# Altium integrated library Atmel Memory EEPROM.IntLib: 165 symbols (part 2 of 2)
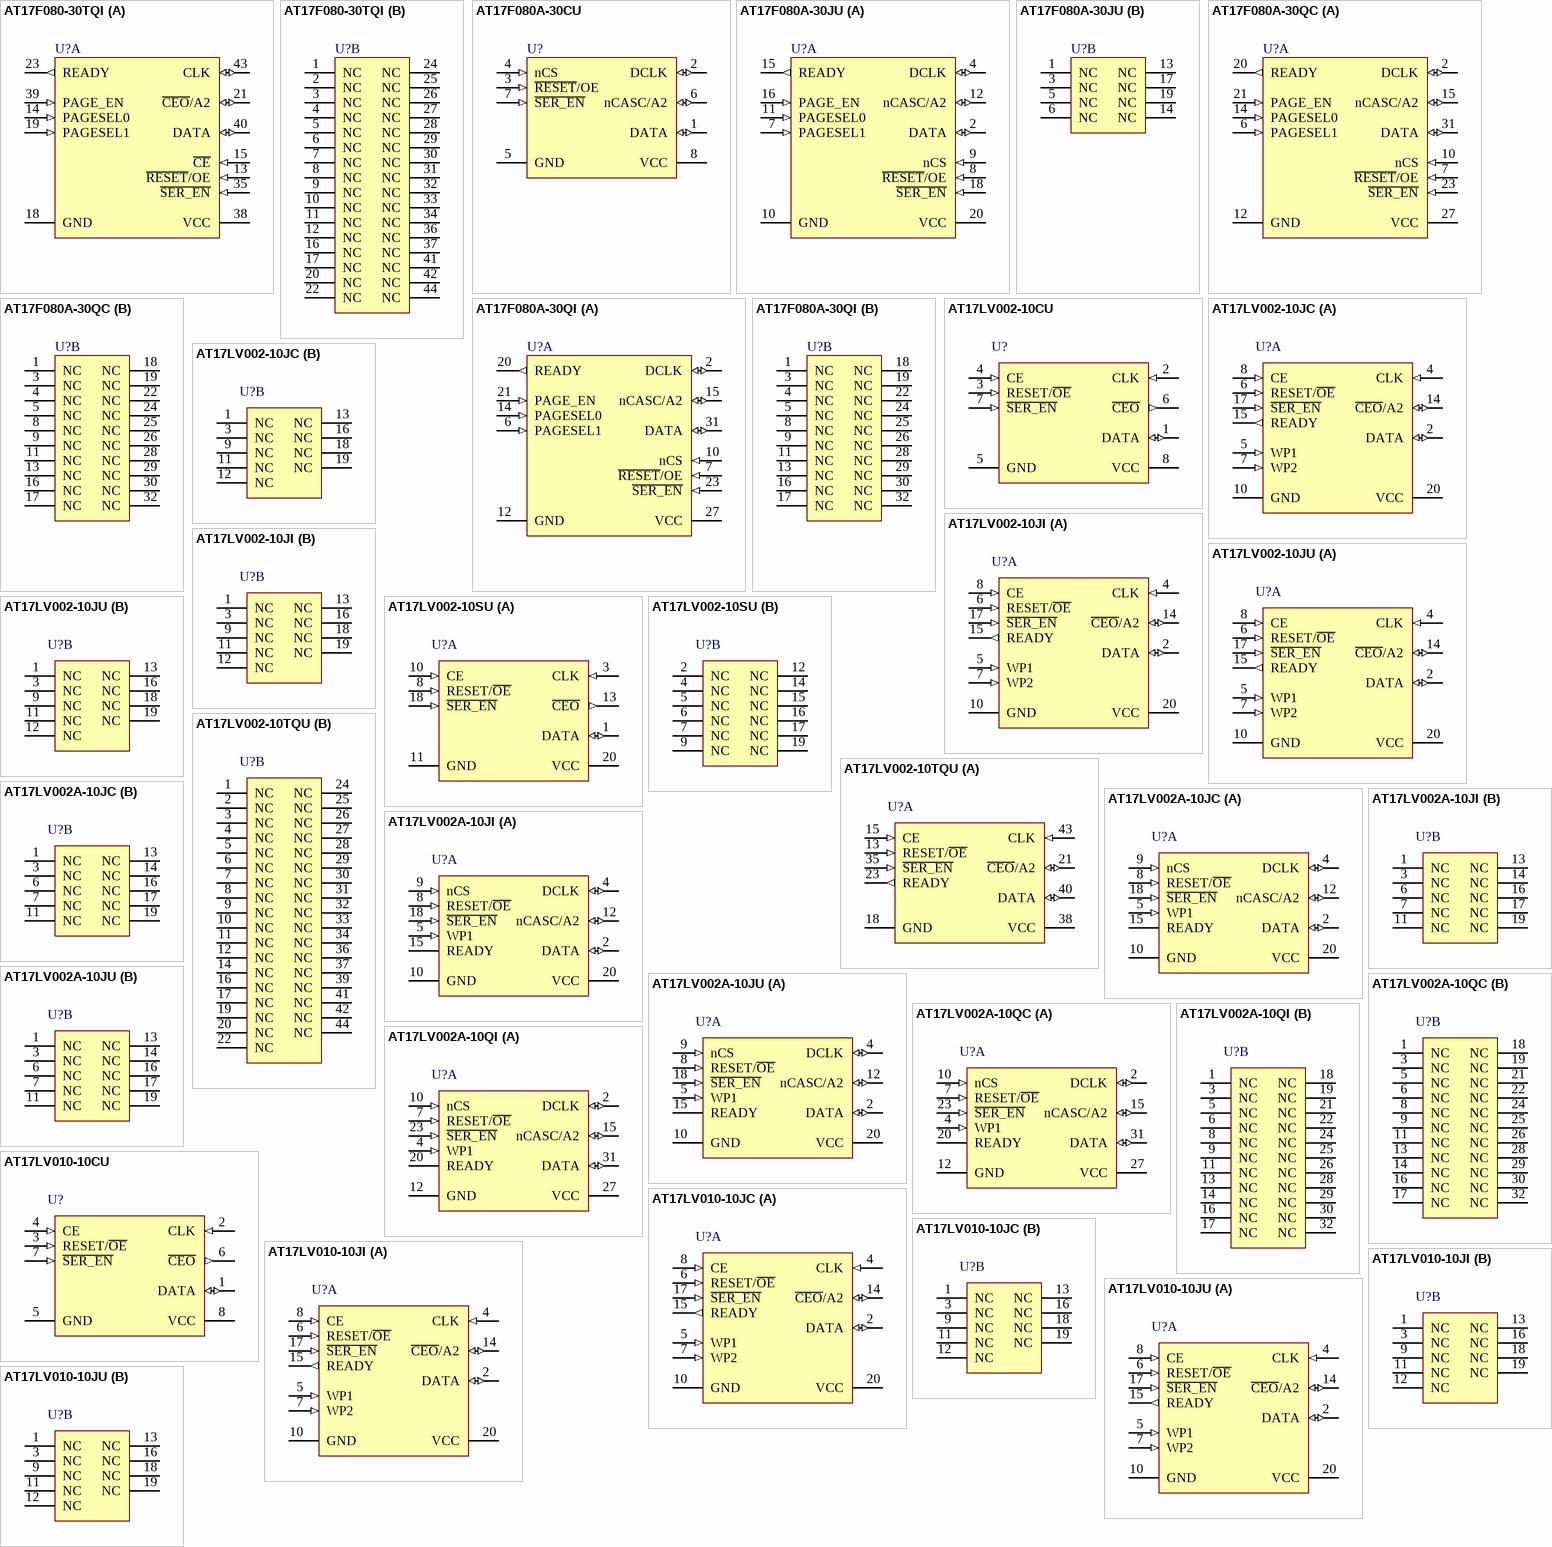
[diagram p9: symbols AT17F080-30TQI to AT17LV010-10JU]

## AT17LV010-10JU
designator U?
FPGA Configuration EEPROM Memory, 1-MBit Memory, 20-Pin PLCC, Industrial Grade (-40°C to 85°C), Pb-Free
footprint 20J_N (Leaded Chip Carrier, 20-Leads, Body 9x9mm, Pitch 1.27mm, IPC Medium Density)
footprint 20J_L (Leaded Chip Carrier, 20-Leads, Body 9x9mm, Pitch 1.27mm, IPC High Density)
footprint 20J_M (Leaded Chip Carrier, 20-Leads, Body 9x9mm, Pitch 1.27mm, IPC Low Density)
part A pins: 2 DATA (io), 4 CLK (in), 5 WP1 (in), 6 RESET/~{OE} (in), 7 WP2 (in), 8 CE (in), 10 GND (power), 14 ~{CEO}/A2 (io), 15 READY (out), 17 ~{SER_EN} (in), 20 VCC (power)
part B pins: 1 NC, 3 NC, 9 NC, 11 NC, 12 NC, 13 NC, 16 NC, 18 NC, 19 NC

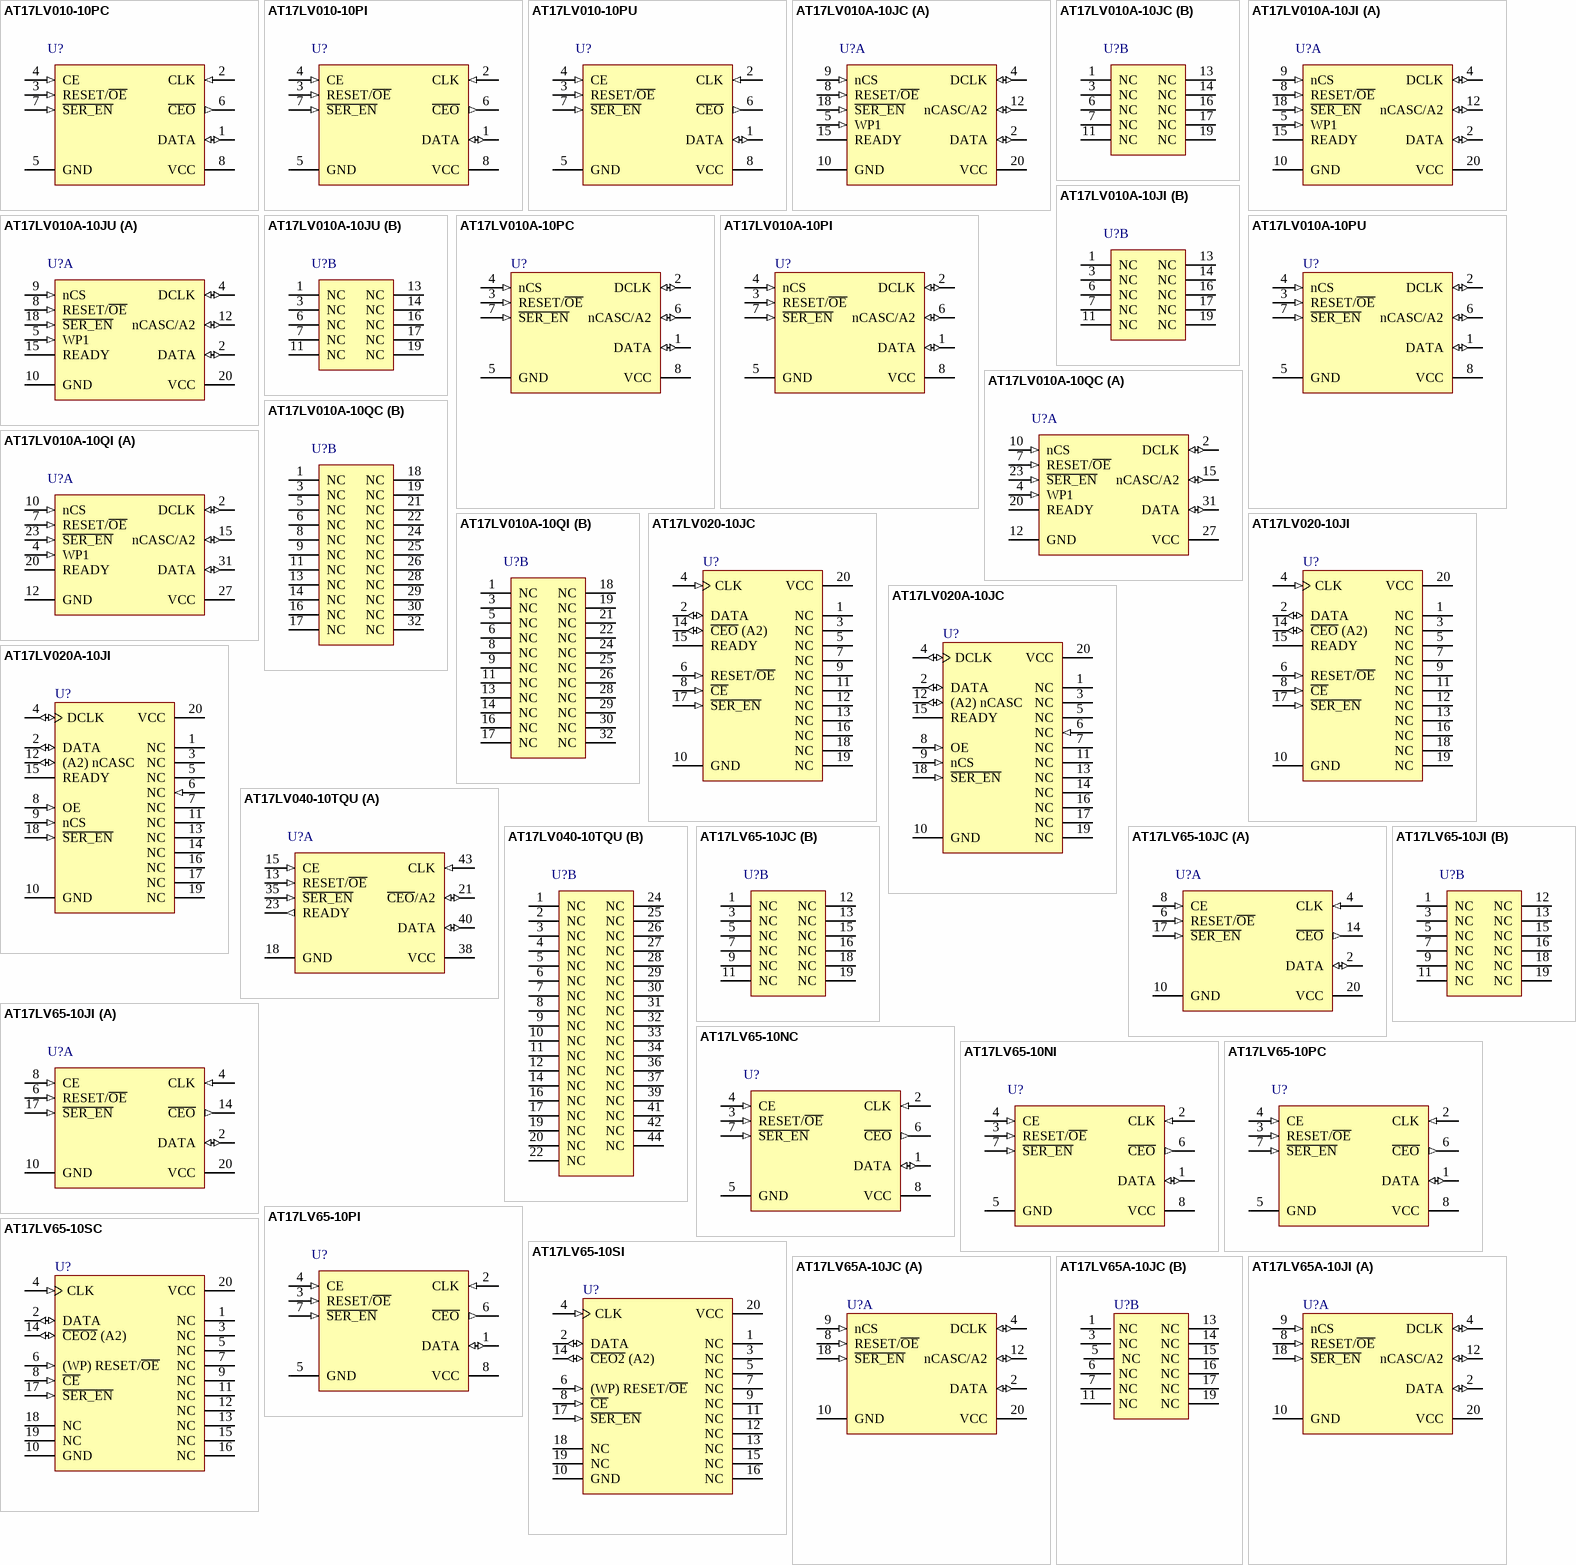
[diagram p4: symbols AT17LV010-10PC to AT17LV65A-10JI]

## AT17LV010-10PC
designator U?
FPGA Configuration EEPROM Memory, 1-MBit Memory, 8-Pin PDIP, Commercial Grade (0°C to 70°C)
footprint 8P3 (DIP, 8-Leads, Row Spacing 7.62mm, Pitch 2.54mm, Body 9.59x6.61mm)
pins: 1 DATA (io), 2 CLK (in), 3 RESET/~{OE} (in), 4 CE (in), 5 GND (power), 6 ~{CEO} (out), 7 ~{SER_EN} (in), 8 VCC (power)

## AT17LV010-10PI
designator U?
FPGA Configuration EEPROM Memory, 1-MBit Memory, 8-Pin PDIP, Industrial Grade (-40°C to 85°C)
footprint 8P3 (DIP, 8-Leads, Row Spacing 7.62mm, Pitch 2.54mm, Body 9.59x6.61mm)
pins: 1 DATA (io), 2 CLK (in), 3 RESET/~{OE} (in), 4 CE (in), 5 GND (power), 6 ~{CEO} (out), 7 ~{SER_EN} (in), 8 VCC (power)

## AT17LV010-10PU
designator U?
FPGA Configuration EEPROM Memory, 1-MBit Memory, 8-Pin PDIP, Industrial Grade (-40°C to 85°C), Pb-Free
footprint 8P3 (DIP, 8-Leads, Row Spacing 7.62mm, Pitch 2.54mm, Body 9.59x6.61mm)
pins: 1 DATA (io), 2 CLK (in), 3 RESET/~{OE} (in), 4 CE (in), 5 GND (power), 6 ~{CEO} (out), 7 ~{SER_EN} (in), 8 VCC (power)

## AT17LV010A-10JC
designator U?
FPGA Configuration EEPROM Memory, 1-MBit Memory, 20-Pin PLCC, Commercial Grade (0°C to 70°C)
footprint 20J_N (Leaded Chip Carrier, 20-Leads, Body 9x9mm, Pitch 1.27mm, IPC Medium Density)
footprint 20J_L (Leaded Chip Carrier, 20-Leads, Body 9x9mm, Pitch 1.27mm, IPC High Density)
footprint 20J_M (Leaded Chip Carrier, 20-Leads, Body 9x9mm, Pitch 1.27mm, IPC Low Density)
part A pins: 2 DATA (io), 4 DCLK (io), 5 WP1 (in), 8 RESET/~{OE} (in), 9 nCS (in), 10 GND (power), 12 nCASC/A2 (io), 15 READY (oc), 18 ~{SER_EN} (in), 20 VCC (power)
part B pins: 1 NC, 3 NC, 6 NC, 7 NC, 11 NC, 13 NC, 14 NC, 16 NC, 17 NC, 19 NC

## AT17LV010A-10JI
designator U?
FPGA Configuration EEPROM Memory, 1-MBit Memory, 20-Pin PLCC, Industrial Grade (-40°C to 85°C)
footprint 20J_N (Leaded Chip Carrier, 20-Leads, Body 9x9mm, Pitch 1.27mm, IPC Medium Density)
footprint 20J_L (Leaded Chip Carrier, 20-Leads, Body 9x9mm, Pitch 1.27mm, IPC High Density)
footprint 20J_M (Leaded Chip Carrier, 20-Leads, Body 9x9mm, Pitch 1.27mm, IPC Low Density)
part A pins: 2 DATA (io), 4 DCLK (io), 5 WP1 (in), 8 RESET/~{OE} (in), 9 nCS (in), 10 GND (power), 12 nCASC/A2 (io), 15 READY (oc), 18 ~{SER_EN} (in), 20 VCC (power)
part B pins: 1 NC, 3 NC, 6 NC, 7 NC, 11 NC, 13 NC, 14 NC, 16 NC, 17 NC, 19 NC

## AT17LV010A-10JU
designator U?
FPGA Configuration EEPROM Memory, 1-MBit Memory, 20-Pin PLCC, Industrial Grade (-40°C to 85°C), Pb-Free
footprint 20J_N (Leaded Chip Carrier, 20-Leads, Body 9x9mm, Pitch 1.27mm, IPC Medium Density)
footprint 20J_L (Leaded Chip Carrier, 20-Leads, Body 9x9mm, Pitch 1.27mm, IPC High Density)
footprint 20J_M (Leaded Chip Carrier, 20-Leads, Body 9x9mm, Pitch 1.27mm, IPC Low Density)
part A pins: 2 DATA (io), 4 DCLK (io), 5 WP1 (in), 8 RESET/~{OE} (in), 9 nCS (in), 10 GND (power), 12 nCASC/A2 (io), 15 READY (oc), 18 ~{SER_EN} (in), 20 VCC (power)
part B pins: 1 NC, 3 NC, 6 NC, 7 NC, 11 NC, 13 NC, 14 NC, 16 NC, 17 NC, 19 NC

## AT17LV010A-10PC
designator U?
FPGA Configuration EEPROM Memory, 1-MBit Memory, 8-Pin PDIP, Commercial Grade (0°C to 70°C)
footprint 8P3 (DIP, 8-Leads, Row Spacing 7.62mm, Pitch 2.54mm, Body 9.59x6.61mm)
pins: 1 DATA (io), 2 DCLK (io), 3 RESET/~{OE} (in), 4 nCS (in), 5 GND (power), 6 nCASC/A2 (io), 7 ~{SER_EN} (in), 8 VCC (power)

## AT17LV010A-10PI
designator U?
FPGA Configuration EEPROM Memory, 1-MBit Memory, 8-Pin PDIP, Industrial Grade (-40°C to 85°C)
footprint 8P3 (DIP, 8-Leads, Row Spacing 7.62mm, Pitch 2.54mm, Body 9.59x6.61mm)
pins: 1 DATA (io), 2 DCLK (io), 3 RESET/~{OE} (in), 4 nCS (in), 5 GND (power), 6 nCASC/A2 (io), 7 ~{SER_EN} (in), 8 VCC (power)

## AT17LV010A-10PU
designator U?
FPGA Configuration EEPROM Memory, 1-MBit Memory, 8-Pin PDIP, Industrial Grade (-40°C to 85°C), Pb-Free
footprint 8P3 (DIP, 8-Leads, Row Spacing 7.62mm, Pitch 2.54mm, Body 9.59x6.61mm)
pins: 1 DATA (io), 2 DCLK (io), 3 RESET/~{OE} (in), 4 nCS (in), 5 GND (power), 6 nCASC/A2 (io), 7 ~{SER_EN} (in), 8 VCC (power)

## AT17LV010A-10QC
designator U?
FPGA Configuration EEPROM Memory, 1-MBit Memory, 32-Pin TQFP, Commercial Grade (0°C to 70°C)
footprint 32A_N (Thin QFP, 32-Leads, Body 7x7mm, Pitch 0.8mm, IPC Medium Density)
footprint 32A_L (Thin QFP, 32-Leads, Body 7x7mm, Pitch 0.8mm, IPC High Density)
footprint 32A_M (Thin QFP, 32-Leads, Body 7x7mm, Pitch 0.8mm, IPC Low Density)
part A pins: 2 DCLK (io), 4 WP1 (in), 7 RESET/~{OE} (in), 10 nCS (in), 12 GND (power), 15 nCASC/A2 (io), 20 READY (oc), 23 ~{SER_EN} (in), 27 VCC (power), 31 DATA (io)
part B pins: 1 NC, 3 NC, 5 NC, 6 NC, 8 NC, 9 NC, 11 NC, 13 NC, 14 NC, 16 NC, 17 NC, 18 NC, 19 NC, 21 NC, 22 NC, 24 NC, 25 NC, 26 NC, 28 NC, 29 NC, 30 NC, 32 NC

## AT17LV010A-10QI
designator U?
FPGA Configuration EEPROM Memory, 1-MBit Memory, 32-Pin TQFP, Industrial Grade (-40°C to 85°C)
footprint 32A_N (Thin QFP, 32-Leads, Body 7x7mm, Pitch 0.8mm, IPC Medium Density)
footprint 32A_L (Thin QFP, 32-Leads, Body 7x7mm, Pitch 0.8mm, IPC High Density)
footprint 32A_M (Thin QFP, 32-Leads, Body 7x7mm, Pitch 0.8mm, IPC Low Density)
part A pins: 2 DCLK (io), 4 WP1 (in), 7 RESET/~{OE} (in), 10 nCS (in), 12 GND (power), 15 nCASC/A2 (io), 20 READY (oc), 23 ~{SER_EN} (in), 27 VCC (power), 31 DATA (io)
part B pins: 1 NC, 3 NC, 5 NC, 6 NC, 8 NC, 9 NC, 11 NC, 13 NC, 14 NC, 16 NC, 17 NC, 18 NC, 19 NC, 21 NC, 22 NC, 24 NC, 25 NC, 26 NC, 28 NC, 29 NC, 30 NC, 32 NC

## AT17LV020-10JC
designator U?
FPGA Configuration EEPROM 2M Memory; ComponentAvailability: Check status with vendor
footprint 20J_N (Leaded Chip Carrier, 20-Leads, Body 9x9mm, Pitch 1.27mm, IPC Medium Density)
footprint 20J_L (Leaded Chip Carrier, 20-Leads, Body 9x9mm, Pitch 1.27mm, IPC High Density)
footprint 20J_M (Leaded Chip Carrier, 20-Leads, Body 9x9mm, Pitch 1.27mm, IPC Low Density)
pins: 1 NC, 2 DATA (io), 3 NC, 4 CLK (in), 5 NC, 6 RESET/~{OE} (in), 7 NC, 8 ~{CE} (in), 9 NC, 10 GND (power), 11 NC, 12 NC, 13 NC, 14 ~{CEO} (A2) (io), 15 READY (oc), 16 NC, 17 ~{SER_EN} (in), 18 NC, 19 NC, 20 VCC (power)

## AT17LV020-10JI
designator U?
FPGA Configuration EEPROM 2M Memory; ComponentAvailability: Check status with vendor
footprint 20J_N (Leaded Chip Carrier, 20-Leads, Body 9x9mm, Pitch 1.27mm, IPC Medium Density)
footprint 20J_L (Leaded Chip Carrier, 20-Leads, Body 9x9mm, Pitch 1.27mm, IPC High Density)
footprint 20J_M (Leaded Chip Carrier, 20-Leads, Body 9x9mm, Pitch 1.27mm, IPC Low Density)
pins: 1 NC, 2 DATA (io), 3 NC, 4 CLK (in), 5 NC, 6 RESET/~{OE} (in), 7 NC, 8 ~{CE} (in), 9 NC, 10 GND (power), 11 NC, 12 NC, 13 NC, 14 ~{CEO} (A2) (io), 15 READY (oc), 16 NC, 17 ~{SER_EN} (in), 18 NC, 19 NC, 20 VCC (power)

## AT17LV020A-10JC
designator U?
FPGA Configuration EEPROM 2M Memory; ComponentAvailability: Check status with vendor
footprint 20J_N (Leaded Chip Carrier, 20-Leads, Body 9x9mm, Pitch 1.27mm, IPC Medium Density)
footprint 20J_L (Leaded Chip Carrier, 20-Leads, Body 9x9mm, Pitch 1.27mm, IPC High Density)
footprint 20J_M (Leaded Chip Carrier, 20-Leads, Body 9x9mm, Pitch 1.27mm, IPC Low Density)
pins: 1 NC, 2 DATA (io), 3 NC, 4 DCLK (io), 5 NC, 6 NC (in), 7 NC, 8 OE (in), 9 nCS (in), 10 GND (power), 11 NC, 12 (A2) nCASC (io), 13 NC, 14 NC, 15 READY (oc), 16 NC, 17 NC, 18 ~{SER_EN} (in), 19 NC, 20 VCC (power)

## AT17LV020A-10JI
designator U?
FPGA Configuration EEPROM 2M Memory; ComponentAvailability: Check status with vendor
footprint 20J_N (Leaded Chip Carrier, 20-Leads, Body 9x9mm, Pitch 1.27mm, IPC Medium Density)
footprint 20J_L (Leaded Chip Carrier, 20-Leads, Body 9x9mm, Pitch 1.27mm, IPC High Density)
footprint 20J_M (Leaded Chip Carrier, 20-Leads, Body 9x9mm, Pitch 1.27mm, IPC Low Density)
pins: 1 NC, 2 DATA (io), 3 NC, 4 DCLK (io), 5 NC, 6 NC (in), 7 NC, 8 OE (in), 9 nCS (in), 10 GND (power), 11 NC, 12 (A2) nCASC (io), 13 NC, 14 NC, 15 READY (oc), 16 NC, 17 NC, 18 ~{SER_EN} (in), 19 NC, 20 VCC (power)

## AT17LV040-10TQU
designator U?
FPGA Configuration EEPROM Memory, 4-MBit Memory, 44-Pin TQFP, Industrial Grade (-40°C to 85°C), Pb-Free
footprint 44A_N (Thin QFP, 44-Leads, Body 10x10mm, Pitch 0.8mm, IPC Medium Density)
footprint 44A_L (Thin QFP, 44-Leads, Body 10x10mm, Pitch 0.8mm, IPC High Density)
footprint 44A_M (Thin QFP, 44-Leads, Body 10x10mm, Pitch 0.8mm, IPC Low Density)
part A pins: 13 RESET/~{OE} (in), 15 CE (in), 18 GND (power), 21 ~{CEO}/A2 (io), 23 READY (out), 35 ~{SER_EN} (in), 38 VCC (power), 40 DATA (io), 43 CLK (in)
part B pins: 1 NC, 2 NC, 3 NC, 4 NC, 5 NC, 6 NC, 7 NC, 8 NC, 9 NC, 10 NC, 11 NC, 12 NC, 14 NC, 16 NC, 17 NC, 19 NC, 20 NC, 22 NC, 24 NC, 25 NC, 26 NC, 27 NC, 28 NC, 29 NC, 30 NC, 31 NC, 32 NC, 33 NC, 34 NC, 36 NC, 37 NC, 39 NC, 41 NC, 42 NC, 44 NC

## AT17LV65-10JC
designator U?
FPGA Configuration EEPROM Memory, 64-KBit Memory, 20-Pin PLCC, Commercial Grade (0°C to 70°C)
footprint 20J_N (Leaded Chip Carrier, 20-Leads, Body 9x9mm, Pitch 1.27mm, IPC Medium Density)
footprint 20J_L (Leaded Chip Carrier, 20-Leads, Body 9x9mm, Pitch 1.27mm, IPC High Density)
footprint 20J_M (Leaded Chip Carrier, 20-Leads, Body 9x9mm, Pitch 1.27mm, IPC Low Density)
part A pins: 2 DATA (io), 4 CLK (in), 6 RESET/~{OE} (in), 8 CE (in), 10 GND (power), 14 ~{CEO} (out), 17 ~{SER_EN} (in), 20 VCC (power)
part B pins: 1 NC, 3 NC, 5 NC, 7 NC, 9 NC, 11 NC, 12 NC, 13 NC, 15 NC, 16 NC, 18 NC, 19 NC

## AT17LV65-10JI
designator U?
FPGA Configuration EEPROM Memory, 64-KBit Memory, 20-Pin PLCC, Industrial Grade (-40°C to 85°C)
footprint 20J_N (Leaded Chip Carrier, 20-Leads, Body 9x9mm, Pitch 1.27mm, IPC Medium Density)
footprint 20J_L (Leaded Chip Carrier, 20-Leads, Body 9x9mm, Pitch 1.27mm, IPC High Density)
footprint 20J_M (Leaded Chip Carrier, 20-Leads, Body 9x9mm, Pitch 1.27mm, IPC Low Density)
part A pins: 2 DATA (io), 4 CLK (in), 6 RESET/~{OE} (in), 8 CE (in), 10 GND (power), 14 ~{CEO} (out), 17 ~{SER_EN} (in), 20 VCC (power)
part B pins: 1 NC, 3 NC, 5 NC, 7 NC, 9 NC, 11 NC, 12 NC, 13 NC, 15 NC, 16 NC, 18 NC, 19 NC

## AT17LV65-10NC
designator U?
FPGA Configuration EEPROM Memory, 64-KBit Memory, 8-Pin SOIC, Commercial Grade (0°C to 70°C)
footprint 8S1_N (SOIC, 8-Leads, Body 4.9x3.9mm, Pitch 1.27mm, IPC Medium Density)
footprint 8S1_L (SOIC, 8-Leads, Body 4.9x3.9mm, Pitch 1.27mm, IPC High Density)
footprint 8S1_M (SOIC, 8-Leads, Body 4.9x3.9mm, Pitch 1.27mm, IPC Low Density)
pins: 1 DATA (io), 2 CLK (in), 3 RESET/~{OE} (in), 4 CE (in), 5 GND (power), 6 ~{CEO} (out), 7 ~{SER_EN} (in), 8 VCC (power)

## AT17LV65-10NI
designator U?
FPGA Configuration EEPROM Memory, 64-KBit Memory, 8-Pin SOIC, Industrial Grade (-40°C to 85°C)
footprint 8S1_N (SOIC, 8-Leads, Body 4.9x3.9mm, Pitch 1.27mm, IPC Medium Density)
footprint 8S1_L (SOIC, 8-Leads, Body 4.9x3.9mm, Pitch 1.27mm, IPC High Density)
footprint 8S1_M (SOIC, 8-Leads, Body 4.9x3.9mm, Pitch 1.27mm, IPC Low Density)
pins: 1 DATA (io), 2 CLK (in), 3 RESET/~{OE} (in), 4 CE (in), 5 GND (power), 6 ~{CEO} (out), 7 ~{SER_EN} (in), 8 VCC (power)

## AT17LV65-10PC
designator U?
FPGA Configuration EEPROM Memory, 64-KBit Memory, 8-Pin PDIP, Commercial Grade (0°C to 70°C)
footprint 8P3 (DIP, 8-Leads, Row Spacing 7.62mm, Pitch 2.54mm, Body 9.59x6.61mm)
pins: 1 DATA (io), 2 CLK (in), 3 RESET/~{OE} (in), 4 CE (in), 5 GND (power), 6 ~{CEO} (out), 7 ~{SER_EN} (in), 8 VCC (power)

## AT17LV65-10PI
designator U?
FPGA Configuration EEPROM Memory, 64-KBit Memory, 8-Pin PDIP, Industrial Grade (-40°C to 85°C)
footprint 8P3 (DIP, 8-Leads, Row Spacing 7.62mm, Pitch 2.54mm, Body 9.59x6.61mm)
pins: 1 DATA (io), 2 CLK (in), 3 RESET/~{OE} (in), 4 CE (in), 5 GND (power), 6 ~{CEO} (out), 7 ~{SER_EN} (in), 8 VCC (power)

## AT17LV65-10SC
designator U?
FPGA Configuration EEPROM 64K Memory; ComponentAvailability: Check status with vendor
footprint 20S_N (SOIC, 20-Leads, Body 12.8x7.5mm, Pitch 1.27mm, IPC Medium Density)
footprint 20S_L (SOIC, 20-Leads, Body 12.8x7.5mm, Pitch 1.27mm, IPC High Density)
footprint 20S_M (SOIC, 20-Leads, Body 12.8x7.5mm, Pitch 1.27mm, IPC Low Density)
pins: 1 NC, 2 DATA (io), 3 NC, 4 CLK (in), 5 NC, 6 (WP) RESET/~{OE} (in), 7 NC, 8 ~{CE} (in), 9 NC, 10 GND (power), 11 NC, 12 NC, 13 NC, 14 ~{CEO2} (A2) (io), 15 NC, 16 NC, 17 ~{SER_EN} (in), 18 NC, 19 NC, 20 VCC (power)

## AT17LV65-10SI
designator U?
FPGA Configuration EEPROM 64K Memory; ComponentAvailability: Check status with vendor
footprint 20S_N (SOIC, 20-Leads, Body 12.8x7.5mm, Pitch 1.27mm, IPC Medium Density)
footprint 20S_L (SOIC, 20-Leads, Body 12.8x7.5mm, Pitch 1.27mm, IPC High Density)
footprint 20S_M (SOIC, 20-Leads, Body 12.8x7.5mm, Pitch 1.27mm, IPC Low Density)
pins: 1 NC, 2 DATA (io), 3 NC, 4 CLK (in), 5 NC, 6 (WP) RESET/~{OE} (in), 7 NC, 8 ~{CE} (in), 9 NC, 10 GND (power), 11 NC, 12 NC, 13 NC, 14 ~{CEO2} (A2) (io), 15 NC, 16 NC, 17 ~{SER_EN} (in), 18 NC, 19 NC, 20 VCC (power)

## AT17LV65A-10JC
designator U?
FPGA Configuration EEPROM Memory, 64-KBit Memory, 20-Pin PLCC, Commercial Grade (0°C to 70°C)
footprint 20J_N (Leaded Chip Carrier, 20-Leads, Body 9x9mm, Pitch 1.27mm, IPC Medium Density)
footprint 20J_L (Leaded Chip Carrier, 20-Leads, Body 9x9mm, Pitch 1.27mm, IPC High Density)
footprint 20J_M (Leaded Chip Carrier, 20-Leads, Body 9x9mm, Pitch 1.27mm, IPC Low Density)
part A pins: 2 DATA (io), 4 DCLK (io), 8 RESET/~{OE} (in), 9 nCS (in), 10 GND (power), 12 nCASC/A2 (io), 18 ~{SER_EN} (in), 20 VCC (power)
part B pins: 1 NC, 3 NC, 5 NC, 6 NC, 7 NC, 11 NC, 13 NC, 14 NC, 15 NC, 16 NC, 17 NC, 19 NC

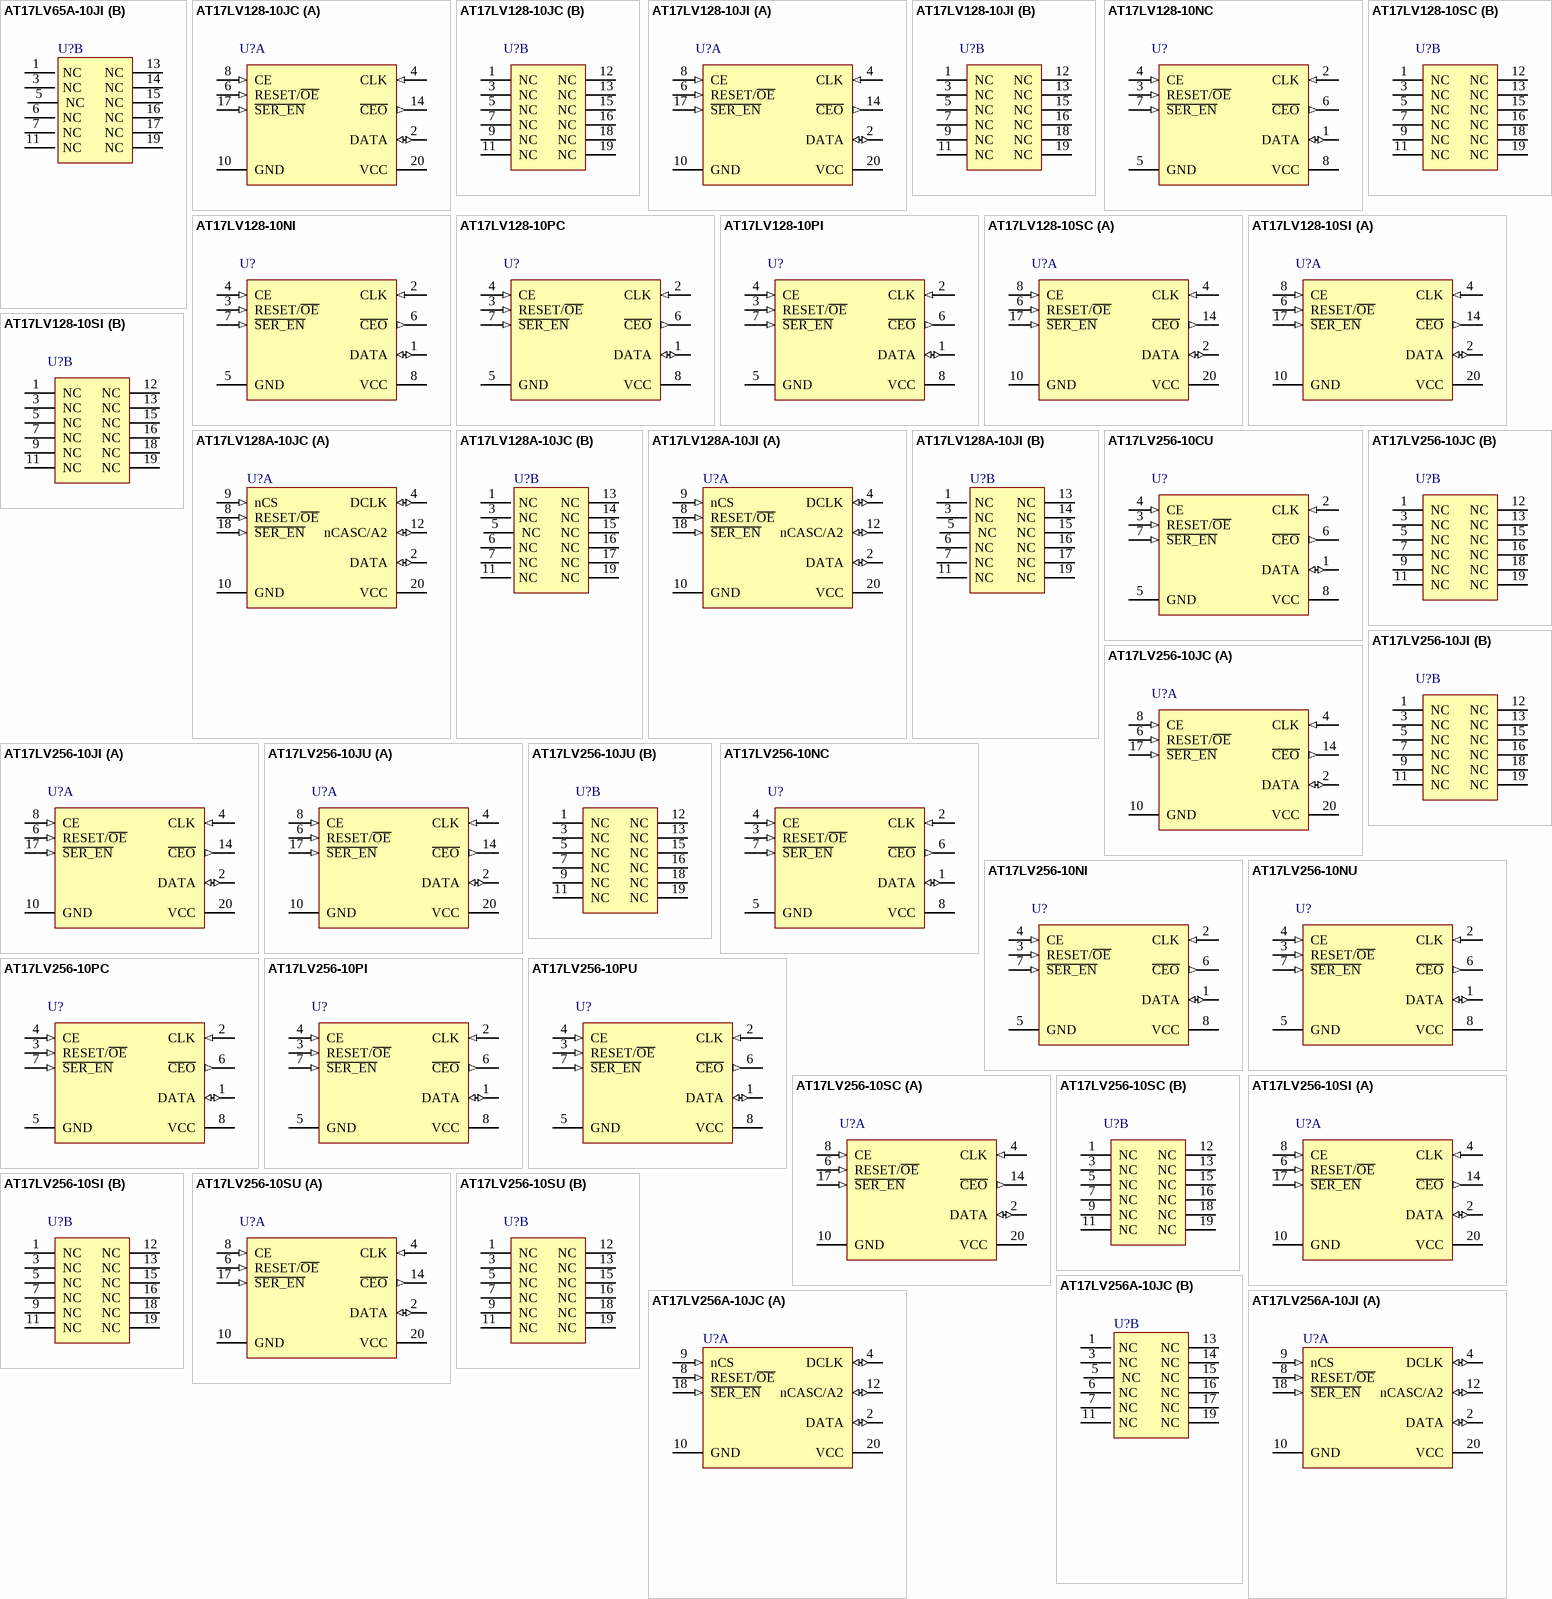
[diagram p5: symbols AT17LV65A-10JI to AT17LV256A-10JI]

## AT17LV65A-10JI
designator U?
FPGA Configuration EEPROM Memory, 64-KBit Memory, 20-Pin PLCC, Industrial Grade (-40°C to 85°C)
footprint 20J_N (Leaded Chip Carrier, 20-Leads, Body 9x9mm, Pitch 1.27mm, IPC Medium Density)
footprint 20J_L (Leaded Chip Carrier, 20-Leads, Body 9x9mm, Pitch 1.27mm, IPC High Density)
footprint 20J_M (Leaded Chip Carrier, 20-Leads, Body 9x9mm, Pitch 1.27mm, IPC Low Density)
part A pins: 2 DATA (io), 4 DCLK (io), 8 RESET/~{OE} (in), 9 nCS (in), 10 GND (power), 12 nCASC/A2 (io), 18 ~{SER_EN} (in), 20 VCC (power)
part B pins: 1 NC, 3 NC, 5 NC, 6 NC, 7 NC, 11 NC, 13 NC, 14 NC, 15 NC, 16 NC, 17 NC, 19 NC

## AT17LV128-10JC
designator U?
FPGA Configuration EEPROM Memory, 128-KBit Memory, 20-Pin PLCC, Commercial Grade (0°C to 70°C)
footprint 20J_N (Leaded Chip Carrier, 20-Leads, Body 9x9mm, Pitch 1.27mm, IPC Medium Density)
footprint 20J_L (Leaded Chip Carrier, 20-Leads, Body 9x9mm, Pitch 1.27mm, IPC High Density)
footprint 20J_M (Leaded Chip Carrier, 20-Leads, Body 9x9mm, Pitch 1.27mm, IPC Low Density)
part A pins: 2 DATA (io), 4 CLK (in), 6 RESET/~{OE} (in), 8 CE (in), 10 GND (power), 14 ~{CEO} (out), 17 ~{SER_EN} (in), 20 VCC (power)
part B pins: 1 NC, 3 NC, 5 NC, 7 NC, 9 NC, 11 NC, 12 NC, 13 NC, 15 NC, 16 NC, 18 NC, 19 NC

## AT17LV128-10JI
designator U?
FPGA Configuration EEPROM Memory, 128-KBit Memory, 20-Pin PLCC, Industrial Grade (-40°C to 85°C)
footprint 20J_N (Leaded Chip Carrier, 20-Leads, Body 9x9mm, Pitch 1.27mm, IPC Medium Density)
footprint 20J_L (Leaded Chip Carrier, 20-Leads, Body 9x9mm, Pitch 1.27mm, IPC High Density)
footprint 20J_M (Leaded Chip Carrier, 20-Leads, Body 9x9mm, Pitch 1.27mm, IPC Low Density)
part A pins: 2 DATA (io), 4 CLK (in), 6 RESET/~{OE} (in), 8 CE (in), 10 GND (power), 14 ~{CEO} (out), 17 ~{SER_EN} (in), 20 VCC (power)
part B pins: 1 NC, 3 NC, 5 NC, 7 NC, 9 NC, 11 NC, 12 NC, 13 NC, 15 NC, 16 NC, 18 NC, 19 NC

## AT17LV128-10NC
designator U?
FPGA Configuration EEPROM Memory, 128-KBit Memory, 8-Pin SOIC, Commercial Grade (0°C to 70°C)
footprint 8S1_N (SOIC, 8-Leads, Body 4.9x3.9mm, Pitch 1.27mm, IPC Medium Density)
footprint 8S1_L (SOIC, 8-Leads, Body 4.9x3.9mm, Pitch 1.27mm, IPC High Density)
footprint 8S1_M (SOIC, 8-Leads, Body 4.9x3.9mm, Pitch 1.27mm, IPC Low Density)
pins: 1 DATA (io), 2 CLK (in), 3 RESET/~{OE} (in), 4 CE (in), 5 GND (power), 6 ~{CEO} (out), 7 ~{SER_EN} (in), 8 VCC (power)

## AT17LV128-10NI
designator U?
FPGA Configuration EEPROM Memory, 128-KBit Memory, 8-Pin SOIC, Industrial Grade (-40°C to 85°C)
footprint 8S1_N (SOIC, 8-Leads, Body 4.9x3.9mm, Pitch 1.27mm, IPC Medium Density)
footprint 8S1_L (SOIC, 8-Leads, Body 4.9x3.9mm, Pitch 1.27mm, IPC High Density)
footprint 8S1_M (SOIC, 8-Leads, Body 4.9x3.9mm, Pitch 1.27mm, IPC Low Density)
pins: 1 DATA (io), 2 CLK (in), 3 RESET/~{OE} (in), 4 CE (in), 5 GND (power), 6 ~{CEO} (out), 7 ~{SER_EN} (in), 8 VCC (power)

## AT17LV128-10PC
designator U?
FPGA Configuration EEPROM Memory, 128-KBit Memory, 8-Pin PDIP, Commercial Grade (0°C to 70°C)
footprint 8P3 (DIP, 8-Leads, Row Spacing 7.62mm, Pitch 2.54mm, Body 9.59x6.61mm)
pins: 1 DATA (io), 2 CLK (in), 3 RESET/~{OE} (in), 4 CE (in), 5 GND (power), 6 ~{CEO} (out), 7 ~{SER_EN} (in), 8 VCC (power)

## AT17LV128-10PI
designator U?
FPGA Configuration EEPROM Memory, 128-KBit Memory, 8-Pin PDIP, Industrial Grade (-40°C to 85°C)
footprint 8P3 (DIP, 8-Leads, Row Spacing 7.62mm, Pitch 2.54mm, Body 9.59x6.61mm)
pins: 1 DATA (io), 2 CLK (in), 3 RESET/~{OE} (in), 4 CE (in), 5 GND (power), 6 ~{CEO} (out), 7 ~{SER_EN} (in), 8 VCC (power)

## AT17LV128-10SC
designator U?
FPGA Configuration EEPROM Memory, 128-KBit Memory, 20-Pin SOIC, Commercial Grade (0°C to 70°C)
footprint 20S2_N (SOIC, 20-Leads, Body 12.8x7.5mm, Pitch 1.27mm, IPC Medium Density)
footprint 20S2_L (SOIC, 20-Leads, Body 12.8x7.5mm, Pitch 1.27mm, IPC High Density)
footprint 20S2_M (SOIC, 20-Leads, Body 12.8x7.5mm, Pitch 1.27mm, IPC Low Density)
part A pins: 2 DATA (io), 4 CLK (in), 6 RESET/~{OE} (in), 8 CE (in), 10 GND (power), 14 ~{CEO} (out), 17 ~{SER_EN} (in), 20 VCC (power)
part B pins: 1 NC, 3 NC, 5 NC, 7 NC, 9 NC, 11 NC, 12 NC, 13 NC, 15 NC, 16 NC, 18 NC, 19 NC

## AT17LV128-10SI
designator U?
FPGA Configuration EEPROM Memory, 128-KBit Memory, 20-Pin SOIC, Industrial Grade (-40°C to 85°C)
footprint 20S2_N (SOIC, 20-Leads, Body 12.8x7.5mm, Pitch 1.27mm, IPC Medium Density)
footprint 20S2_L (SOIC, 20-Leads, Body 12.8x7.5mm, Pitch 1.27mm, IPC High Density)
footprint 20S2_M (SOIC, 20-Leads, Body 12.8x7.5mm, Pitch 1.27mm, IPC Low Density)
part A pins: 2 DATA (io), 4 CLK (in), 6 RESET/~{OE} (in), 8 CE (in), 10 GND (power), 14 ~{CEO} (out), 17 ~{SER_EN} (in), 20 VCC (power)
part B pins: 1 NC, 3 NC, 5 NC, 7 NC, 9 NC, 11 NC, 12 NC, 13 NC, 15 NC, 16 NC, 18 NC, 19 NC

## AT17LV128A-10JC
designator U?
FPGA Configuration EEPROM Memory, 128-KBit Memory, 20-Pin PLCC, Commercial Grade (0°C to 70°C)
footprint 20J_N (Leaded Chip Carrier, 20-Leads, Body 9x9mm, Pitch 1.27mm, IPC Medium Density)
footprint 20J_L (Leaded Chip Carrier, 20-Leads, Body 9x9mm, Pitch 1.27mm, IPC High Density)
footprint 20J_M (Leaded Chip Carrier, 20-Leads, Body 9x9mm, Pitch 1.27mm, IPC Low Density)
part A pins: 2 DATA (io), 4 DCLK (io), 8 RESET/~{OE} (in), 9 nCS (in), 10 GND (power), 12 nCASC/A2 (io), 18 ~{SER_EN} (in), 20 VCC (power)
part B pins: 1 NC, 3 NC, 5 NC, 6 NC, 7 NC, 11 NC, 13 NC, 14 NC, 15 NC, 16 NC, 17 NC, 19 NC

## AT17LV128A-10JI
designator U?
FPGA Configuration EEPROM Memory, 128-KBit Memory, 20-Pin PLCC, Industrial Grade (-40°C to 85°C)
footprint 20J_N (Leaded Chip Carrier, 20-Leads, Body 9x9mm, Pitch 1.27mm, IPC Medium Density)
footprint 20J_L (Leaded Chip Carrier, 20-Leads, Body 9x9mm, Pitch 1.27mm, IPC High Density)
footprint 20J_M (Leaded Chip Carrier, 20-Leads, Body 9x9mm, Pitch 1.27mm, IPC Low Density)
part A pins: 2 DATA (io), 4 DCLK (io), 8 RESET/~{OE} (in), 9 nCS (in), 10 GND (power), 12 nCASC/A2 (io), 18 ~{SER_EN} (in), 20 VCC (power)
part B pins: 1 NC, 3 NC, 5 NC, 6 NC, 7 NC, 11 NC, 13 NC, 14 NC, 15 NC, 16 NC, 17 NC, 19 NC

## AT17LV256-10CU
designator U?
FPGA Configuration EEPROM Memory, 256-KBit Memory, 8-Pin LAP, Industrial Grade (-40°C to 85°C), Pb-Free
footprint 8CN4 (SON, 8-Leads, Body 6x6 mm, Pitch 1.27mm)
pins: 1 DATA (io), 2 CLK (in), 3 RESET/~{OE} (in), 4 CE (in), 5 GND (power), 6 ~{CEO} (out), 7 ~{SER_EN} (in), 8 VCC (power)

## AT17LV256-10JC
designator U?
FPGA Configuration EEPROM Memory, 256-KBit Memory, 20-Pin PLCC, Commercial Grade (0°C to 70°C)
footprint 20J_N (Leaded Chip Carrier, 20-Leads, Body 9x9mm, Pitch 1.27mm, IPC Medium Density)
footprint 20J_L (Leaded Chip Carrier, 20-Leads, Body 9x9mm, Pitch 1.27mm, IPC High Density)
footprint 20J_M (Leaded Chip Carrier, 20-Leads, Body 9x9mm, Pitch 1.27mm, IPC Low Density)
part A pins: 2 DATA (io), 4 CLK (in), 6 RESET/~{OE} (in), 8 CE (in), 10 GND (power), 14 ~{CEO} (out), 17 ~{SER_EN} (in), 20 VCC (power)
part B pins: 1 NC, 3 NC, 5 NC, 7 NC, 9 NC, 11 NC, 12 NC, 13 NC, 15 NC, 16 NC, 18 NC, 19 NC

## AT17LV256-10JI
designator U?
FPGA Configuration EEPROM Memory, 256-KBit Memory, 20-Pin PLCC, Industrial Grade (-40°C to 85°C)
footprint 20J_N (Leaded Chip Carrier, 20-Leads, Body 9x9mm, Pitch 1.27mm, IPC Medium Density)
footprint 20J_L (Leaded Chip Carrier, 20-Leads, Body 9x9mm, Pitch 1.27mm, IPC High Density)
footprint 20J_M (Leaded Chip Carrier, 20-Leads, Body 9x9mm, Pitch 1.27mm, IPC Low Density)
part A pins: 2 DATA (io), 4 CLK (in), 6 RESET/~{OE} (in), 8 CE (in), 10 GND (power), 14 ~{CEO} (out), 17 ~{SER_EN} (in), 20 VCC (power)
part B pins: 1 NC, 3 NC, 5 NC, 7 NC, 9 NC, 11 NC, 12 NC, 13 NC, 15 NC, 16 NC, 18 NC, 19 NC

## AT17LV256-10JU
designator U?
FPGA Configuration EEPROM Memory, 256-KBit Memory, 20-Pin PLCC, Industrial Grade (-40°C to 85°C), Pb-Free
footprint 20J_N (Leaded Chip Carrier, 20-Leads, Body 9x9mm, Pitch 1.27mm, IPC Medium Density)
footprint 20J_L (Leaded Chip Carrier, 20-Leads, Body 9x9mm, Pitch 1.27mm, IPC High Density)
footprint 20J_M (Leaded Chip Carrier, 20-Leads, Body 9x9mm, Pitch 1.27mm, IPC Low Density)
part A pins: 2 DATA (io), 4 CLK (in), 6 RESET/~{OE} (in), 8 CE (in), 10 GND (power), 14 ~{CEO} (out), 17 ~{SER_EN} (in), 20 VCC (power)
part B pins: 1 NC, 3 NC, 5 NC, 7 NC, 9 NC, 11 NC, 12 NC, 13 NC, 15 NC, 16 NC, 18 NC, 19 NC

## AT17LV256-10NC
designator U?
FPGA Configuration EEPROM Memory, 256-KBit Memory, 8-Pin SOIC, Commercial Grade (0°C to 70°C)
footprint 8S1_N (SOIC, 8-Leads, Body 4.9x3.9mm, Pitch 1.27mm, IPC Medium Density)
footprint 8S1_L (SOIC, 8-Leads, Body 4.9x3.9mm, Pitch 1.27mm, IPC High Density)
footprint 8S1_M (SOIC, 8-Leads, Body 4.9x3.9mm, Pitch 1.27mm, IPC Low Density)
pins: 1 DATA (io), 2 CLK (in), 3 RESET/~{OE} (in), 4 CE (in), 5 GND (power), 6 ~{CEO} (out), 7 ~{SER_EN} (in), 8 VCC (power)

## AT17LV256-10NI
designator U?
FPGA Configuration EEPROM Memory, 256-KBit Memory, 8-Pin SOIC, Industrial Grade (-40°C to 85°C)
footprint 8S1_N (SOIC, 8-Leads, Body 4.9x3.9mm, Pitch 1.27mm, IPC Medium Density)
footprint 8S1_L (SOIC, 8-Leads, Body 4.9x3.9mm, Pitch 1.27mm, IPC High Density)
footprint 8S1_M (SOIC, 8-Leads, Body 4.9x3.9mm, Pitch 1.27mm, IPC Low Density)
pins: 1 DATA (io), 2 CLK (in), 3 RESET/~{OE} (in), 4 CE (in), 5 GND (power), 6 ~{CEO} (out), 7 ~{SER_EN} (in), 8 VCC (power)

## AT17LV256-10NU
designator U?
FPGA Configuration EEPROM Memory, 256-KBit Memory, 8-Pin SOIC, Industrial Grade (-40°C to 85°C), Pb-Free
footprint 8S1_N (SOIC, 8-Leads, Body 4.9x3.9mm, Pitch 1.27mm, IPC Medium Density)
footprint 8S1_L (SOIC, 8-Leads, Body 4.9x3.9mm, Pitch 1.27mm, IPC High Density)
footprint 8S1_M (SOIC, 8-Leads, Body 4.9x3.9mm, Pitch 1.27mm, IPC Low Density)
pins: 1 DATA (io), 2 CLK (in), 3 RESET/~{OE} (in), 4 CE (in), 5 GND (power), 6 ~{CEO} (out), 7 ~{SER_EN} (in), 8 VCC (power)

## AT17LV256-10PC
designator U?
FPGA Configuration EEPROM Memory, 256-KBit Memory, 8-Pin PDIP, Commercial Grade (0°C to 70°C)
footprint 8P3 (DIP, 8-Leads, Row Spacing 7.62mm, Pitch 2.54mm, Body 9.59x6.61mm)
pins: 1 DATA (io), 2 CLK (in), 3 RESET/~{OE} (in), 4 CE (in), 5 GND (power), 6 ~{CEO} (out), 7 ~{SER_EN} (in), 8 VCC (power)

## AT17LV256-10PI
designator U?
FPGA Configuration EEPROM Memory, 256-KBit Memory, 8-Pin PDIP, Industrial Grade (-40°C to 85°C)
footprint 8P3 (DIP, 8-Leads, Row Spacing 7.62mm, Pitch 2.54mm, Body 9.59x6.61mm)
pins: 1 DATA (io), 2 CLK (in), 3 RESET/~{OE} (in), 4 CE (in), 5 GND (power), 6 ~{CEO} (out), 7 ~{SER_EN} (in), 8 VCC (power)

## AT17LV256-10PU
designator U?
FPGA Configuration EEPROM Memory, 256-KBit Memory, 8-Pin PDIP, Industrial Grade (-40°C to 85°C), Pb-Free
footprint 8P3 (DIP, 8-Leads, Row Spacing 7.62mm, Pitch 2.54mm, Body 9.59x6.61mm)
pins: 1 DATA (io), 2 CLK (in), 3 RESET/~{OE} (in), 4 CE (in), 5 GND (power), 6 ~{CEO} (out), 7 ~{SER_EN} (in), 8 VCC (power)

## AT17LV256-10SC
designator U?
FPGA Configuration EEPROM Memory, 256-KBit Memory, 20-Pin SOIC, Commercial Grade (0°C to 70°C)
footprint 20S2_N (SOIC, 20-Leads, Body 12.8x7.5mm, Pitch 1.27mm, IPC Medium Density)
footprint 20S2_L (SOIC, 20-Leads, Body 12.8x7.5mm, Pitch 1.27mm, IPC High Density)
footprint 20S2_M (SOIC, 20-Leads, Body 12.8x7.5mm, Pitch 1.27mm, IPC Low Density)
part A pins: 2 DATA (io), 4 CLK (in), 6 RESET/~{OE} (in), 8 CE (in), 10 GND (power), 14 ~{CEO} (out), 17 ~{SER_EN} (in), 20 VCC (power)
part B pins: 1 NC, 3 NC, 5 NC, 7 NC, 9 NC, 11 NC, 12 NC, 13 NC, 15 NC, 16 NC, 18 NC, 19 NC

## AT17LV256-10SI
designator U?
FPGA Configuration EEPROM Memory, 256-KBit Memory, 20-Pin SOIC, Industrial Grade (-40°C to 85°C)
footprint 20S2_N (SOIC, 20-Leads, Body 12.8x7.5mm, Pitch 1.27mm, IPC Medium Density)
footprint 20S2_L (SOIC, 20-Leads, Body 12.8x7.5mm, Pitch 1.27mm, IPC High Density)
footprint 20S2_M (SOIC, 20-Leads, Body 12.8x7.5mm, Pitch 1.27mm, IPC Low Density)
part A pins: 2 DATA (io), 4 CLK (in), 6 RESET/~{OE} (in), 8 CE (in), 10 GND (power), 14 ~{CEO} (out), 17 ~{SER_EN} (in), 20 VCC (power)
part B pins: 1 NC, 3 NC, 5 NC, 7 NC, 9 NC, 11 NC, 12 NC, 13 NC, 15 NC, 16 NC, 18 NC, 19 NC

## AT17LV256-10SU
designator U?
FPGA Configuration EEPROM Memory, 256-KBit Memory, 20-Pin SOIC, Industrial Grade (-40°C to 85°C), Pb-Free
footprint 20S2_N (SOIC, 20-Leads, Body 12.8x7.5mm, Pitch 1.27mm, IPC Medium Density)
footprint 20S2_L (SOIC, 20-Leads, Body 12.8x7.5mm, Pitch 1.27mm, IPC High Density)
footprint 20S2_M (SOIC, 20-Leads, Body 12.8x7.5mm, Pitch 1.27mm, IPC Low Density)
part A pins: 2 DATA (io), 4 CLK (in), 6 RESET/~{OE} (in), 8 CE (in), 10 GND (power), 14 ~{CEO} (out), 17 ~{SER_EN} (in), 20 VCC (power)
part B pins: 1 NC, 3 NC, 5 NC, 7 NC, 9 NC, 11 NC, 12 NC, 13 NC, 15 NC, 16 NC, 18 NC, 19 NC

## AT17LV256A-10JC
designator U?
FPGA Configuration EEPROM Memory, 256-KBit Memory, 20-Pin PLCC, Commercial Grade (0°C to 70°C)
footprint 20J_N (Leaded Chip Carrier, 20-Leads, Body 9x9mm, Pitch 1.27mm, IPC Medium Density)
footprint 20J_L (Leaded Chip Carrier, 20-Leads, Body 9x9mm, Pitch 1.27mm, IPC High Density)
footprint 20J_M (Leaded Chip Carrier, 20-Leads, Body 9x9mm, Pitch 1.27mm, IPC Low Density)
part A pins: 2 DATA (io), 4 DCLK (io), 8 RESET/~{OE} (in), 9 nCS (in), 10 GND (power), 12 nCASC/A2 (io), 18 ~{SER_EN} (in), 20 VCC (power)
part B pins: 1 NC, 3 NC, 5 NC, 6 NC, 7 NC, 11 NC, 13 NC, 14 NC, 15 NC, 16 NC, 17 NC, 19 NC

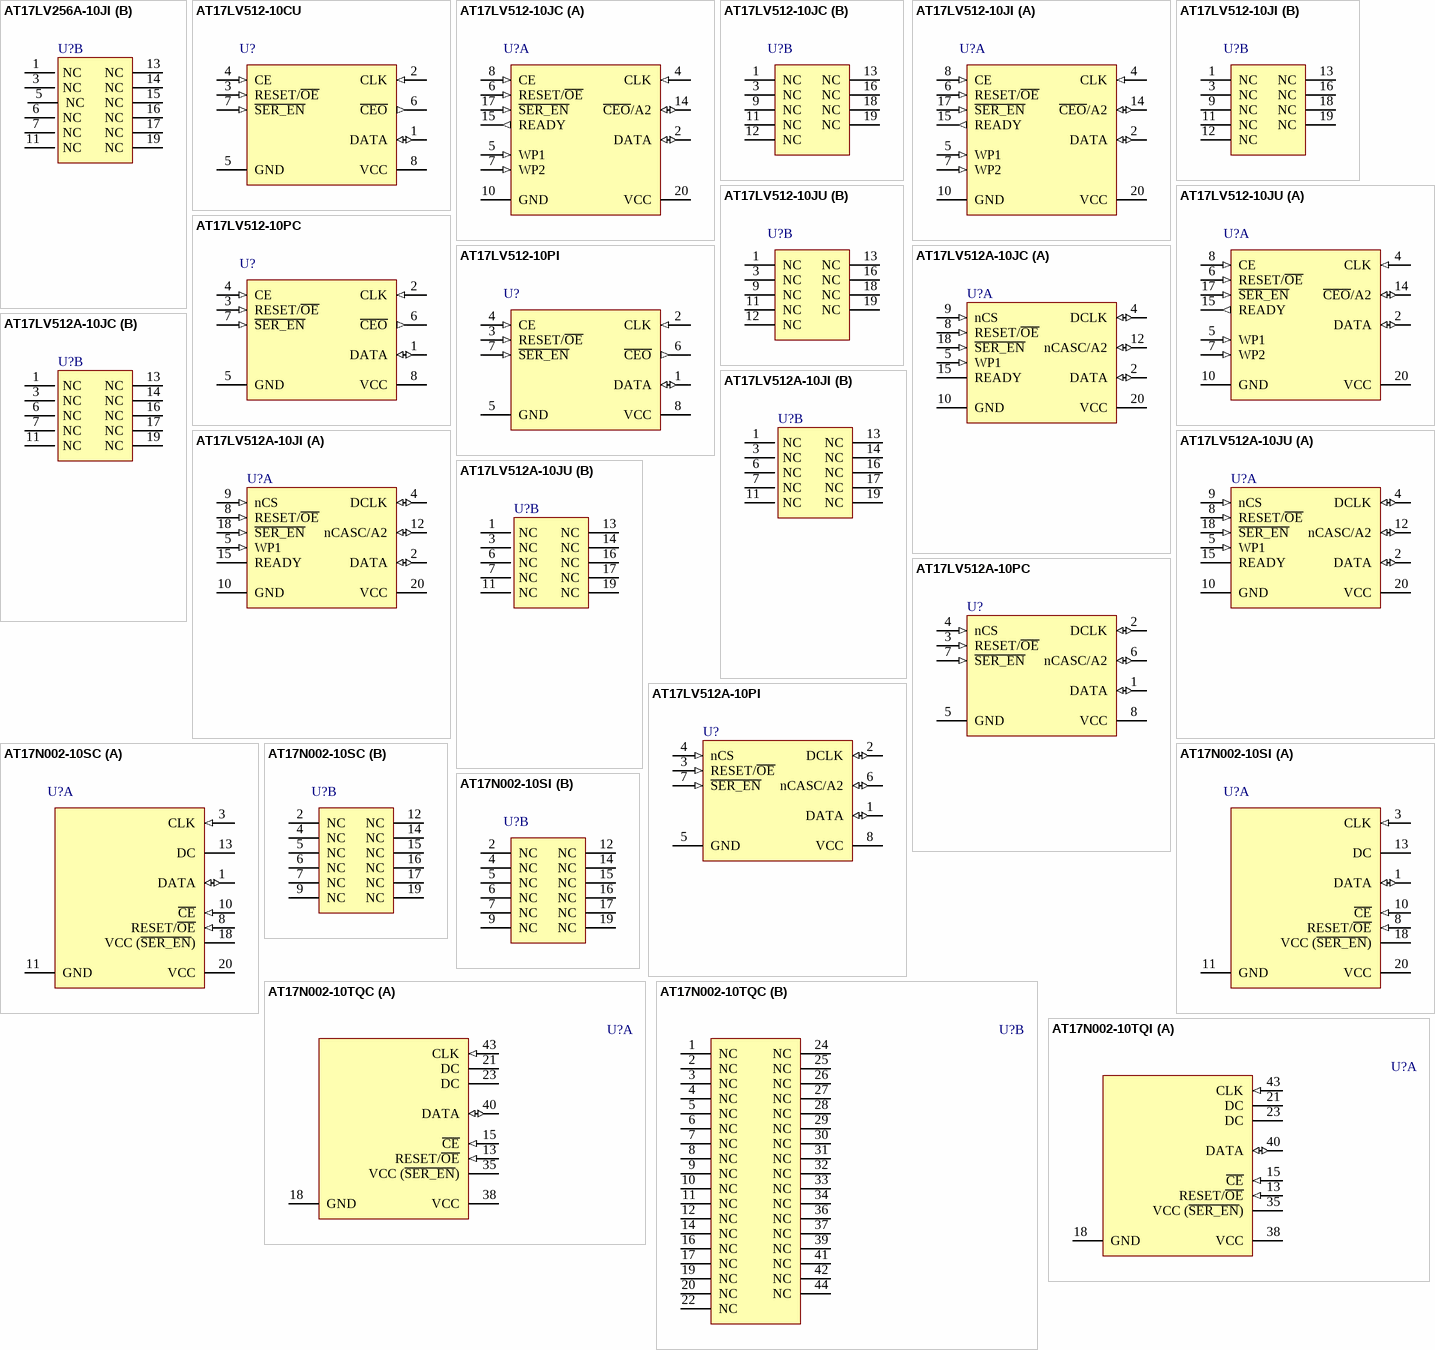
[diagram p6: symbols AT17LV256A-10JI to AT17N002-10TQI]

## AT17LV256A-10JI
designator U?
FPGA Configuration EEPROM Memory, 256-KBit Memory, 20-Pin PLCC, Industrial Grade (-40°C to 85°C)
footprint 20J_N (Leaded Chip Carrier, 20-Leads, Body 9x9mm, Pitch 1.27mm, IPC Medium Density)
footprint 20J_L (Leaded Chip Carrier, 20-Leads, Body 9x9mm, Pitch 1.27mm, IPC High Density)
footprint 20J_M (Leaded Chip Carrier, 20-Leads, Body 9x9mm, Pitch 1.27mm, IPC Low Density)
part A pins: 2 DATA (io), 4 DCLK (io), 8 RESET/~{OE} (in), 9 nCS (in), 10 GND (power), 12 nCASC/A2 (io), 18 ~{SER_EN} (in), 20 VCC (power)
part B pins: 1 NC, 3 NC, 5 NC, 6 NC, 7 NC, 11 NC, 13 NC, 14 NC, 15 NC, 16 NC, 17 NC, 19 NC

## AT17LV512-10CU
designator U?
FPGA Configuration EEPROM Memory, 512-KBit Memory, 8-Pin LAP, Industrial Grade (-40°C to 85°C), Pb-Free
footprint 8CN4 (SON, 8-Leads, Body 6x6 mm, Pitch 1.27mm)
pins: 1 DATA (io), 2 CLK (in), 3 RESET/~{OE} (in), 4 CE (in), 5 GND (power), 6 ~{CEO} (out), 7 ~{SER_EN} (in), 8 VCC (power)

## AT17LV512-10JC
designator U?
FPGA Configuration EEPROM Memory, 512-KBit Memory, 20-Pin PLCC, Commercial Grade (0°C to 70°C)
footprint 20J_N (Leaded Chip Carrier, 20-Leads, Body 9x9mm, Pitch 1.27mm, IPC Medium Density)
footprint 20J_L (Leaded Chip Carrier, 20-Leads, Body 9x9mm, Pitch 1.27mm, IPC High Density)
footprint 20J_M (Leaded Chip Carrier, 20-Leads, Body 9x9mm, Pitch 1.27mm, IPC Low Density)
part A pins: 2 DATA (io), 4 CLK (in), 5 WP1 (in), 6 RESET/~{OE} (in), 7 WP2 (in), 8 CE (in), 10 GND (power), 14 ~{CEO}/A2 (io), 15 READY (out), 17 ~{SER_EN} (in), 20 VCC (power)
part B pins: 1 NC, 3 NC, 9 NC, 11 NC, 12 NC, 13 NC, 16 NC, 18 NC, 19 NC

## AT17LV512-10JI
designator U?
FPGA Configuration EEPROM Memory, 512-KBit Memory, 20-Pin PLCC, Industrial Grade (-40°C to 85°C)
footprint 20J_N (Leaded Chip Carrier, 20-Leads, Body 9x9mm, Pitch 1.27mm, IPC Medium Density)
footprint 20J_L (Leaded Chip Carrier, 20-Leads, Body 9x9mm, Pitch 1.27mm, IPC High Density)
footprint 20J_M (Leaded Chip Carrier, 20-Leads, Body 9x9mm, Pitch 1.27mm, IPC Low Density)
part A pins: 2 DATA (io), 4 CLK (in), 5 WP1 (in), 6 RESET/~{OE} (in), 7 WP2 (in), 8 CE (in), 10 GND (power), 14 ~{CEO}/A2 (io), 15 READY (out), 17 ~{SER_EN} (in), 20 VCC (power)
part B pins: 1 NC, 3 NC, 9 NC, 11 NC, 12 NC, 13 NC, 16 NC, 18 NC, 19 NC

## AT17LV512-10JU
designator U?
FPGA Configuration EEPROM Memory, 512-KBit Memory, 20-Pin PLCC, Industrial Grade (-40°C to 85°C), Pb-Free
footprint 20J_N (Leaded Chip Carrier, 20-Leads, Body 9x9mm, Pitch 1.27mm, IPC Medium Density)
footprint 20J_L (Leaded Chip Carrier, 20-Leads, Body 9x9mm, Pitch 1.27mm, IPC High Density)
footprint 20J_M (Leaded Chip Carrier, 20-Leads, Body 9x9mm, Pitch 1.27mm, IPC Low Density)
part A pins: 2 DATA (io), 4 CLK (in), 5 WP1 (in), 6 RESET/~{OE} (in), 7 WP2 (in), 8 CE (in), 10 GND (power), 14 ~{CEO}/A2 (io), 15 READY (out), 17 ~{SER_EN} (in), 20 VCC (power)
part B pins: 1 NC, 3 NC, 9 NC, 11 NC, 12 NC, 13 NC, 16 NC, 18 NC, 19 NC

## AT17LV512-10PC
designator U?
FPGA Configuration EEPROM Memory, 512-KBit Memory, 8-Pin PDIP, Commercial Grade (0°C to 70°C)
footprint 8P3 (DIP, 8-Leads, Row Spacing 7.62mm, Pitch 2.54mm, Body 9.59x6.61mm)
pins: 1 DATA (io), 2 CLK (in), 3 RESET/~{OE} (in), 4 CE (in), 5 GND (power), 6 ~{CEO} (out), 7 ~{SER_EN} (in), 8 VCC (power)

## AT17LV512-10PI
designator U?
FPGA Configuration EEPROM Memory, 512-KBit Memory, 8-Pin PDIP, Industrial Grade (-40°C to 85°C)
footprint 8P3 (DIP, 8-Leads, Row Spacing 7.62mm, Pitch 2.54mm, Body 9.59x6.61mm)
pins: 1 DATA (io), 2 CLK (in), 3 RESET/~{OE} (in), 4 CE (in), 5 GND (power), 6 ~{CEO} (out), 7 ~{SER_EN} (in), 8 VCC (power)

## AT17LV512A-10JC
designator U?
FPGA Configuration EEPROM Memory, 512-KBit Memory, 20-Pin PLCC, Commercial Grade (0°C to 70°C)
footprint 20J_N (Leaded Chip Carrier, 20-Leads, Body 9x9mm, Pitch 1.27mm, IPC Medium Density)
footprint 20J_L (Leaded Chip Carrier, 20-Leads, Body 9x9mm, Pitch 1.27mm, IPC High Density)
footprint 20J_M (Leaded Chip Carrier, 20-Leads, Body 9x9mm, Pitch 1.27mm, IPC Low Density)
part A pins: 2 DATA (io), 4 DCLK (io), 5 WP1 (in), 8 RESET/~{OE} (in), 9 nCS (in), 10 GND (power), 12 nCASC/A2 (io), 15 READY (oc), 18 ~{SER_EN} (in), 20 VCC (power)
part B pins: 1 NC, 3 NC, 6 NC, 7 NC, 11 NC, 13 NC, 14 NC, 16 NC, 17 NC, 19 NC

## AT17LV512A-10JI
designator U?
FPGA Configuration EEPROM Memory, 512-KBit Memory, 20-Pin PLCC, Industrial Grade (-40°C to 85°C)
footprint 20J_N (Leaded Chip Carrier, 20-Leads, Body 9x9mm, Pitch 1.27mm, IPC Medium Density)
footprint 20J_L (Leaded Chip Carrier, 20-Leads, Body 9x9mm, Pitch 1.27mm, IPC High Density)
footprint 20J_M (Leaded Chip Carrier, 20-Leads, Body 9x9mm, Pitch 1.27mm, IPC Low Density)
part A pins: 2 DATA (io), 4 DCLK (io), 5 WP1 (in), 8 RESET/~{OE} (in), 9 nCS (in), 10 GND (power), 12 nCASC/A2 (io), 15 READY (oc), 18 ~{SER_EN} (in), 20 VCC (power)
part B pins: 1 NC, 3 NC, 6 NC, 7 NC, 11 NC, 13 NC, 14 NC, 16 NC, 17 NC, 19 NC

## AT17LV512A-10JU
designator U?
FPGA Configuration EEPROM Memory, 512-KBit Memory, 20-Pin PLCC, Industrial Grade (-40°C to 85°C), Pb-Free
footprint 20J_N (Leaded Chip Carrier, 20-Leads, Body 9x9mm, Pitch 1.27mm, IPC Medium Density)
footprint 20J_L (Leaded Chip Carrier, 20-Leads, Body 9x9mm, Pitch 1.27mm, IPC High Density)
footprint 20J_M (Leaded Chip Carrier, 20-Leads, Body 9x9mm, Pitch 1.27mm, IPC Low Density)
part A pins: 2 DATA (io), 4 DCLK (io), 5 WP1 (in), 8 RESET/~{OE} (in), 9 nCS (in), 10 GND (power), 12 nCASC/A2 (io), 15 READY (oc), 18 ~{SER_EN} (in), 20 VCC (power)
part B pins: 1 NC, 3 NC, 6 NC, 7 NC, 11 NC, 13 NC, 14 NC, 16 NC, 17 NC, 19 NC

## AT17LV512A-10PC
designator U?
FPGA Configuration EEPROM Memory, 512-KBit Memory, 8-Pin PDIP, Commercial Grade (0°C to 70°C)
footprint 8P3 (DIP, 8-Leads, Row Spacing 7.62mm, Pitch 2.54mm, Body 9.59x6.61mm)
pins: 1 DATA (io), 2 DCLK (io), 3 RESET/~{OE} (in), 4 nCS (in), 5 GND (power), 6 nCASC/A2 (io), 7 ~{SER_EN} (in), 8 VCC (power)

## AT17LV512A-10PI
designator U?
FPGA Configuration EEPROM Memory, 512-KBit Memory, 8-Pin PDIP, Industrial Grade (-40°C to 85°C)
footprint 8P3 (DIP, 8-Leads, Row Spacing 7.62mm, Pitch 2.54mm, Body 9.59x6.61mm)
pins: 1 DATA (io), 2 DCLK (io), 3 RESET/~{OE} (in), 4 nCS (in), 5 GND (power), 6 nCASC/A2 (io), 7 ~{SER_EN} (in), 8 VCC (power)

## AT17N002-10SC
designator U?
FPGA Configuration Memory, 2-MBit Memory, 20Pin SOIC, Commercial Grade (0°C to 70°C)
footprint 20S2_N (SOIC, 20-Leads, Body 12.8x7.5mm, Pitch 1.27mm, IPC Medium Density)
footprint 20S2_L (SOIC, 20-Leads, Body 12.8x7.5mm, Pitch 1.27mm, IPC High Density)
footprint 20S2_M (SOIC, 20-Leads, Body 12.8x7.5mm, Pitch 1.27mm, IPC Low Density)
part A pins: 1 DATA (io), 3 CLK (in), 8 RESET/~{OE} (in), 10 ~{CE} (in), 11 GND (power), 13 DC, 18 VCC (~{SER_EN}) (power), 20 VCC (power)
part B pins: 2 NC, 4 NC, 5 NC, 6 NC, 7 NC, 9 NC, 12 NC, 14 NC, 15 NC, 16 NC, 17 NC, 19 NC

## AT17N002-10SI
designator U?
FPGA Configuration Memory, 2-MBit Memory, 20Pin SOIC, Industrial Grade (-40°C to 85°C)
footprint 20S2_N (SOIC, 20-Leads, Body 12.8x7.5mm, Pitch 1.27mm, IPC Medium Density)
footprint 20S2_L (SOIC, 20-Leads, Body 12.8x7.5mm, Pitch 1.27mm, IPC High Density)
footprint 20S2_M (SOIC, 20-Leads, Body 12.8x7.5mm, Pitch 1.27mm, IPC Low Density)
part A pins: 1 DATA (io), 3 CLK (in), 8 RESET/~{OE} (in), 10 ~{CE} (in), 11 GND (power), 13 DC, 18 VCC (~{SER_EN}) (power), 20 VCC (power)
part B pins: 2 NC, 4 NC, 5 NC, 6 NC, 7 NC, 9 NC, 12 NC, 14 NC, 15 NC, 16 NC, 17 NC, 19 NC

## AT17N002-10TQC
designator U?
FPGA Configuration Memory, 2-MBit Memory, 44-Pin TQFP, Commercial Grade (0°C to 70°C)
footprint 44A_N (Thin QFP, 44-Leads, Body 10x10mm, Pitch 0.8mm, IPC Medium Density)
footprint 44A_L (Thin QFP, 44-Leads, Body 10x10mm, Pitch 0.8mm, IPC High Density)
footprint 44A_M (Thin QFP, 44-Leads, Body 10x10mm, Pitch 0.8mm, IPC Low Density)
part A pins: 13 RESET/~{OE} (in), 15 ~{CE} (in), 18 GND (power), 21 DC, 23 DC, 35 VCC (~{SER_EN}) (power), 38 VCC (power), 40 DATA (io), 43 CLK (in)
part B pins: 1 NC, 2 NC, 3 NC, 4 NC, 5 NC, 6 NC, 7 NC, 8 NC, 9 NC, 10 NC, 11 NC, 12 NC, 14 NC, 16 NC, 17 NC, 19 NC, 20 NC, 22 NC, 24 NC, 25 NC, 26 NC, 27 NC, 28 NC, 29 NC, 30 NC, 31 NC, 32 NC, 33 NC, 34 NC, 36 NC, 37 NC, 39 NC, 41 NC, 42 NC, 44 NC

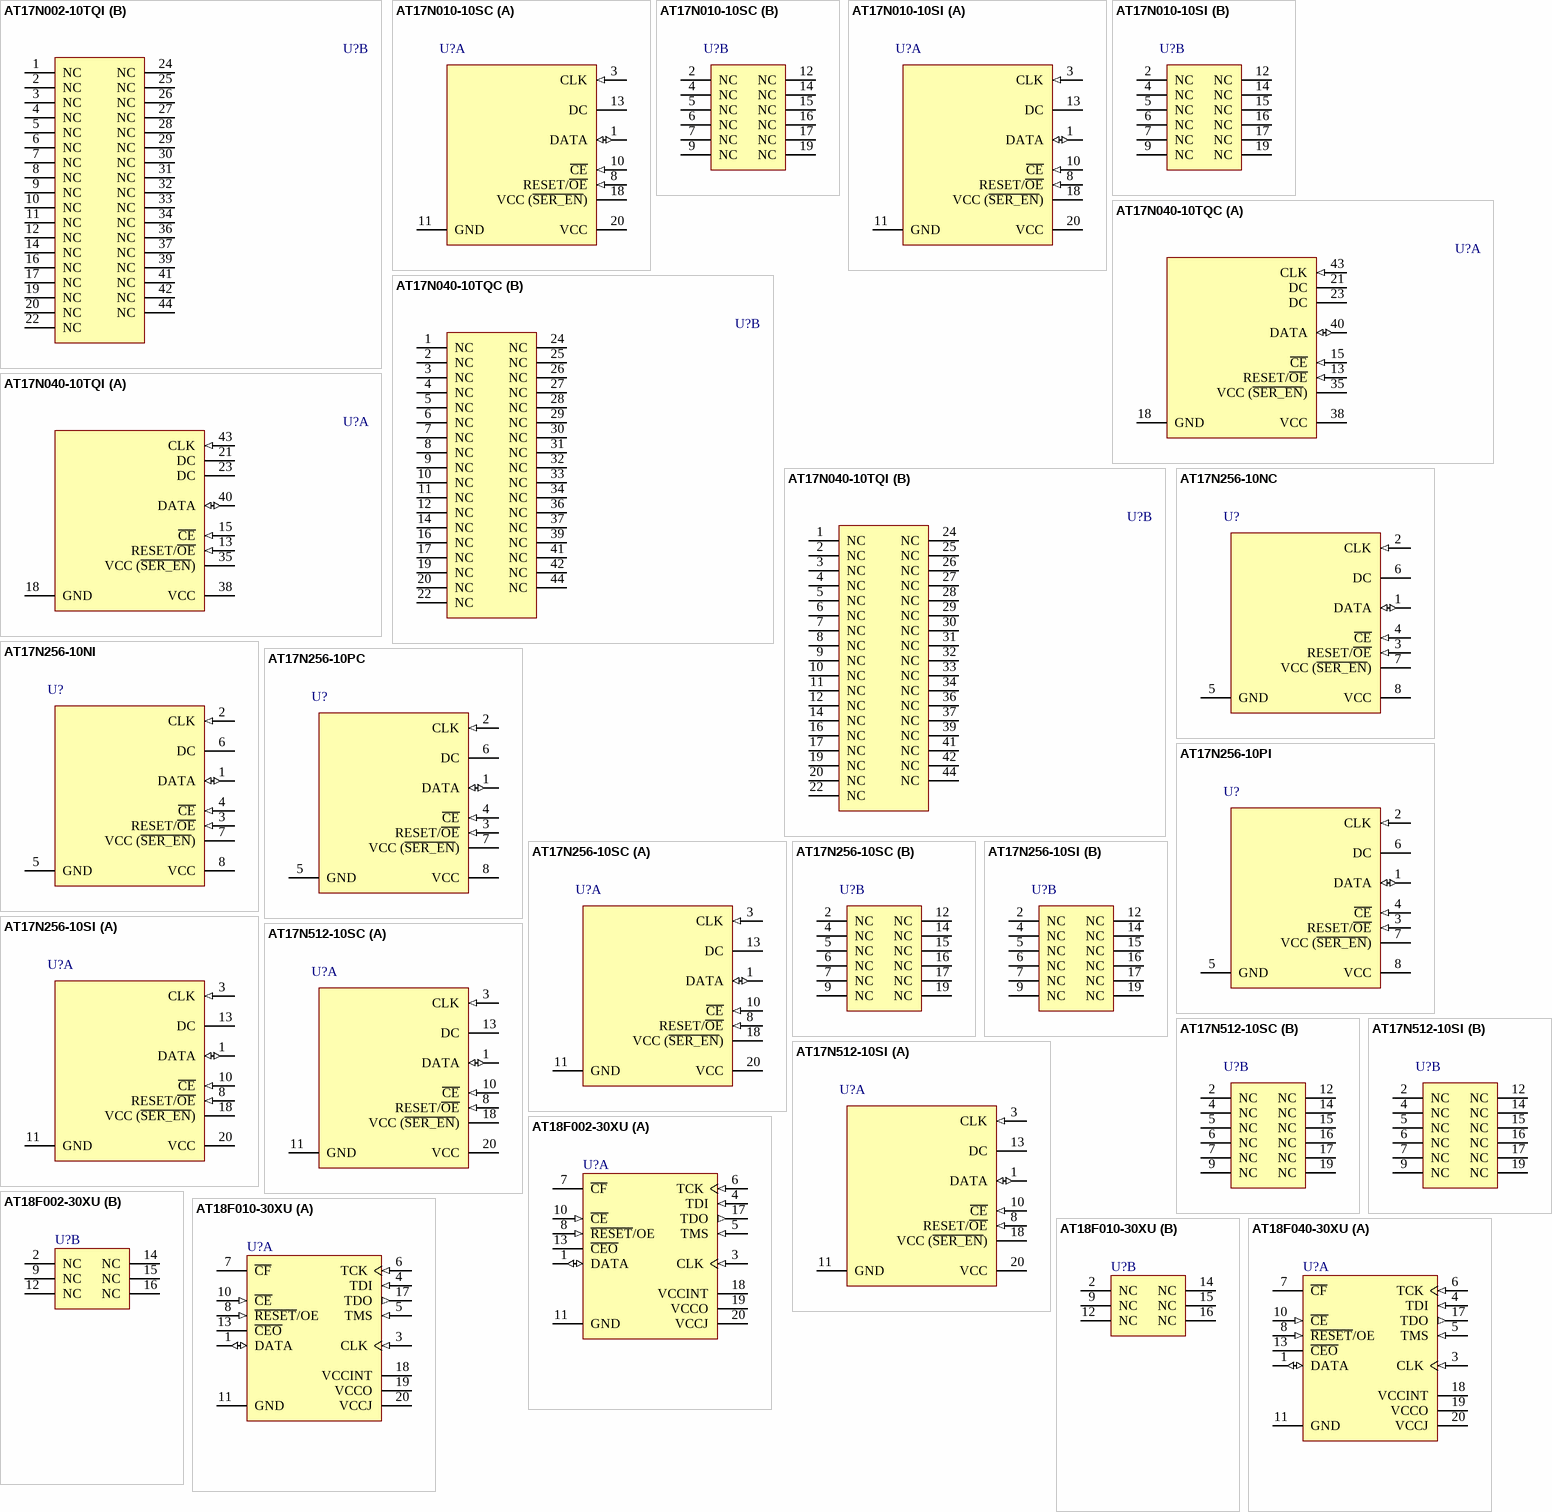
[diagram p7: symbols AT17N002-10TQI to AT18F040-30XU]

## AT17N002-10TQI
designator U?
FPGA Configuration Memory, 2-MBit Memory, 44-Pin TQFP, Industrial Grade (-40°C to 85°C)
footprint 44A_N (Thin QFP, 44-Leads, Body 10x10mm, Pitch 0.8mm, IPC Medium Density)
footprint 44A_L (Thin QFP, 44-Leads, Body 10x10mm, Pitch 0.8mm, IPC High Density)
footprint 44A_M (Thin QFP, 44-Leads, Body 10x10mm, Pitch 0.8mm, IPC Low Density)
part A pins: 13 RESET/~{OE} (in), 15 ~{CE} (in), 18 GND (power), 21 DC, 23 DC, 35 VCC (~{SER_EN}) (power), 38 VCC (power), 40 DATA (io), 43 CLK (in)
part B pins: 1 NC, 2 NC, 3 NC, 4 NC, 5 NC, 6 NC, 7 NC, 8 NC, 9 NC, 10 NC, 11 NC, 12 NC, 14 NC, 16 NC, 17 NC, 19 NC, 20 NC, 22 NC, 24 NC, 25 NC, 26 NC, 27 NC, 28 NC, 29 NC, 30 NC, 31 NC, 32 NC, 33 NC, 34 NC, 36 NC, 37 NC, 39 NC, 41 NC, 42 NC, 44 NC

## AT17N010-10SC
designator U?
FPGA Configuration Memory, 1-MBit Memory, 20Pin SOIC, Commercial Grade (0°C to 70°C)
footprint 20S2_N (SOIC, 20-Leads, Body 12.8x7.5mm, Pitch 1.27mm, IPC Medium Density)
footprint 20S2_L (SOIC, 20-Leads, Body 12.8x7.5mm, Pitch 1.27mm, IPC High Density)
footprint 20S2_M (SOIC, 20-Leads, Body 12.8x7.5mm, Pitch 1.27mm, IPC Low Density)
part A pins: 1 DATA (io), 3 CLK (in), 8 RESET/~{OE} (in), 10 ~{CE} (in), 11 GND (power), 13 DC, 18 VCC (~{SER_EN}) (power), 20 VCC (power)
part B pins: 2 NC, 4 NC, 5 NC, 6 NC, 7 NC, 9 NC, 12 NC, 14 NC, 15 NC, 16 NC, 17 NC, 19 NC

## AT17N010-10SI
designator U?
FPGA Configuration Memory, 1-MBit Memory, 20Pin SOIC, Industrial Grade (-40°C to 85°C)
footprint 20S2_N (SOIC, 20-Leads, Body 12.8x7.5mm, Pitch 1.27mm, IPC Medium Density)
footprint 20S2_L (SOIC, 20-Leads, Body 12.8x7.5mm, Pitch 1.27mm, IPC High Density)
footprint 20S2_M (SOIC, 20-Leads, Body 12.8x7.5mm, Pitch 1.27mm, IPC Low Density)
part A pins: 1 DATA (io), 3 CLK (in), 8 RESET/~{OE} (in), 10 ~{CE} (in), 11 GND (power), 13 DC, 18 VCC (~{SER_EN}) (power), 20 VCC (power)
part B pins: 2 NC, 4 NC, 5 NC, 6 NC, 7 NC, 9 NC, 12 NC, 14 NC, 15 NC, 16 NC, 17 NC, 19 NC

## AT17N040-10TQC
designator U?
FPGA Configuration Memory, 4-MBit Memory, 44-Pin TQFP, Commercial Grade (0°C to 70°C)
footprint 44A_N (Thin QFP, 44-Leads, Body 10x10mm, Pitch 0.8mm, IPC Medium Density)
footprint 44A_L (Thin QFP, 44-Leads, Body 10x10mm, Pitch 0.8mm, IPC High Density)
footprint 44A_M (Thin QFP, 44-Leads, Body 10x10mm, Pitch 0.8mm, IPC Low Density)
part A pins: 13 RESET/~{OE} (in), 15 ~{CE} (in), 18 GND (power), 21 DC, 23 DC, 35 VCC (~{SER_EN}) (power), 38 VCC (power), 40 DATA (io), 43 CLK (in)
part B pins: 1 NC, 2 NC, 3 NC, 4 NC, 5 NC, 6 NC, 7 NC, 8 NC, 9 NC, 10 NC, 11 NC, 12 NC, 14 NC, 16 NC, 17 NC, 19 NC, 20 NC, 22 NC, 24 NC, 25 NC, 26 NC, 27 NC, 28 NC, 29 NC, 30 NC, 31 NC, 32 NC, 33 NC, 34 NC, 36 NC, 37 NC, 39 NC, 41 NC, 42 NC, 44 NC

## AT17N040-10TQI
designator U?
FPGA Configuration Memory, 4-MBit Memory, 44-Pin TQFP, Industrial Grade (-40°C to 85°C)
footprint 44A_N (Thin QFP, 44-Leads, Body 10x10mm, Pitch 0.8mm, IPC Medium Density)
footprint 44A_L (Thin QFP, 44-Leads, Body 10x10mm, Pitch 0.8mm, IPC High Density)
footprint 44A_M (Thin QFP, 44-Leads, Body 10x10mm, Pitch 0.8mm, IPC Low Density)
part A pins: 13 RESET/~{OE} (in), 15 ~{CE} (in), 18 GND (power), 21 DC, 23 DC, 35 VCC (~{SER_EN}) (power), 38 VCC (power), 40 DATA (io), 43 CLK (in)
part B pins: 1 NC, 2 NC, 3 NC, 4 NC, 5 NC, 6 NC, 7 NC, 8 NC, 9 NC, 10 NC, 11 NC, 12 NC, 14 NC, 16 NC, 17 NC, 19 NC, 20 NC, 22 NC, 24 NC, 25 NC, 26 NC, 27 NC, 28 NC, 29 NC, 30 NC, 31 NC, 32 NC, 33 NC, 34 NC, 36 NC, 37 NC, 39 NC, 41 NC, 42 NC, 44 NC

## AT17N256-10NC
designator U?
FPGA Configuration Memory, 256-Kbit Memory, 8-Pin SOIC, Commercial Grade (0°C to 70°C)
footprint 8S1_N (SOIC, 8-Leads, Body 4.9x3.9mm, Pitch 1.27mm, IPC Medium Density)
footprint 8S1_L (SOIC, 8-Leads, Body 4.9x3.9mm, Pitch 1.27mm, IPC High Density)
footprint 8S1_M (SOIC, 8-Leads, Body 4.9x3.9mm, Pitch 1.27mm, IPC Low Density)
pins: 1 DATA (io), 2 CLK (in), 3 RESET/~{OE} (in), 4 ~{CE} (in), 5 GND (power), 6 DC, 7 VCC (~{SER_EN}) (power), 8 VCC (power)

## AT17N256-10NI
designator U?
FPGA Configuration Memory, 256-Kbit Memory, 8-Pin SOIC, Industrial Grade (-40°C to 85°C)
footprint 8S1_N (SOIC, 8-Leads, Body 4.9x3.9mm, Pitch 1.27mm, IPC Medium Density)
footprint 8S1_L (SOIC, 8-Leads, Body 4.9x3.9mm, Pitch 1.27mm, IPC High Density)
footprint 8S1_M (SOIC, 8-Leads, Body 4.9x3.9mm, Pitch 1.27mm, IPC Low Density)
pins: 1 DATA (io), 2 CLK (in), 3 RESET/~{OE} (in), 4 ~{CE} (in), 5 GND (power), 6 DC, 7 VCC (~{SER_EN}) (power), 8 VCC (power)

## AT17N256-10PC
designator U?
FPGA Configuration Memory, 256-Kbit Memory, 8-Pin PDIP, Commercial Grade (0°C to 70°C)
footprint 8P3 (DIP, 8-Leads, Row Spacing 7.62mm, Pitch 2.54mm, Body 9.59x6.61mm)
pins: 1 DATA (io), 2 CLK (in), 3 RESET/~{OE} (in), 4 ~{CE} (in), 5 GND (power), 6 DC, 7 VCC (~{SER_EN}) (power), 8 VCC (power)

## AT17N256-10PI
designator U?
FPGA Configuration Memory, 256-Kbit Memory, 8-Pin PDIP, Industrial Grade (-40°C to 85°C)
footprint 8P3 (DIP, 8-Leads, Row Spacing 7.62mm, Pitch 2.54mm, Body 9.59x6.61mm)
pins: 1 DATA (io), 2 CLK (in), 3 RESET/~{OE} (in), 4 ~{CE} (in), 5 GND (power), 6 DC, 7 VCC (~{SER_EN}) (power), 8 VCC (power)

## AT17N256-10SC
designator U?
FPGA Configuration Memory, 256-Kbit Memory, 20Pin SOIC, Commercial Grade (0°C to 70°C)
footprint 20S2_N (SOIC, 20-Leads, Body 12.8x7.5mm, Pitch 1.27mm, IPC Medium Density)
footprint 20S2_L (SOIC, 20-Leads, Body 12.8x7.5mm, Pitch 1.27mm, IPC High Density)
footprint 20S2_M (SOIC, 20-Leads, Body 12.8x7.5mm, Pitch 1.27mm, IPC Low Density)
part A pins: 1 DATA (io), 3 CLK (in), 8 RESET/~{OE} (in), 10 ~{CE} (in), 11 GND (power), 13 DC, 18 VCC (~{SER_EN}) (power), 20 VCC (power)
part B pins: 2 NC, 4 NC, 5 NC, 6 NC, 7 NC, 9 NC, 12 NC, 14 NC, 15 NC, 16 NC, 17 NC, 19 NC

## AT17N256-10SI
designator U?
FPGA Configuration Memory, 256-Kbit Memory, 20Pin SOIC, Industrial Grade (-40°C to 85°C)
footprint 20S2_N (SOIC, 20-Leads, Body 12.8x7.5mm, Pitch 1.27mm, IPC Medium Density)
footprint 20S2_L (SOIC, 20-Leads, Body 12.8x7.5mm, Pitch 1.27mm, IPC High Density)
footprint 20S2_M (SOIC, 20-Leads, Body 12.8x7.5mm, Pitch 1.27mm, IPC Low Density)
part A pins: 1 DATA (io), 3 CLK (in), 8 RESET/~{OE} (in), 10 ~{CE} (in), 11 GND (power), 13 DC, 18 VCC (~{SER_EN}) (power), 20 VCC (power)
part B pins: 2 NC, 4 NC, 5 NC, 6 NC, 7 NC, 9 NC, 12 NC, 14 NC, 15 NC, 16 NC, 17 NC, 19 NC

## AT17N512-10SC
designator U?
FPGA Configuration Memory, 512-Kbit Memory, 20Pin SOIC, Commercial Grade (0°C to 70°C)
footprint 20S2_N (SOIC, 20-Leads, Body 12.8x7.5mm, Pitch 1.27mm, IPC Medium Density)
footprint 20S2_L (SOIC, 20-Leads, Body 12.8x7.5mm, Pitch 1.27mm, IPC High Density)
footprint 20S2_M (SOIC, 20-Leads, Body 12.8x7.5mm, Pitch 1.27mm, IPC Low Density)
part A pins: 1 DATA (io), 3 CLK (in), 8 RESET/~{OE} (in), 10 ~{CE} (in), 11 GND (power), 13 DC, 18 VCC (~{SER_EN}) (power), 20 VCC (power)
part B pins: 2 NC, 4 NC, 5 NC, 6 NC, 7 NC, 9 NC, 12 NC, 14 NC, 15 NC, 16 NC, 17 NC, 19 NC

## AT17N512-10SI
designator U?
FPGA Configuration Memory, 512-Kbit Memory, 20Pin SOIC, Industrial Grade (-40°C to 85°C)
footprint 20S2_N (SOIC, 20-Leads, Body 12.8x7.5mm, Pitch 1.27mm, IPC Medium Density)
footprint 20S2_L (SOIC, 20-Leads, Body 12.8x7.5mm, Pitch 1.27mm, IPC High Density)
footprint 20S2_M (SOIC, 20-Leads, Body 12.8x7.5mm, Pitch 1.27mm, IPC Low Density)
part A pins: 1 DATA (io), 3 CLK (in), 8 RESET/~{OE} (in), 10 ~{CE} (in), 11 GND (power), 13 DC, 18 VCC (~{SER_EN}) (power), 20 VCC (power)
part B pins: 2 NC, 4 NC, 5 NC, 6 NC, 7 NC, 9 NC, 12 NC, 14 NC, 15 NC, 16 NC, 17 NC, 19 NC

## AT18F002-30XU
designator U?
FPGA Configuration Flash Memory, 2-MBit Memory, 20-Pin TSSOP, Industrial Grade (-40°C to 85°C)
footprint 20A2_N (TSOP, 20-Leads, Body 6.5x4.4mm, Pitch 0.65mm, IPC Medium Density)
footprint 20A2_L (TSOP, 20-Leads, Body 6.5x4.4mm, Pitch 0.65mm, IPC High Density)
footprint 20A2_M (TSOP, 20-Leads, Body 6.5x4.4mm, Pitch 0.65mm, IPC Low Density)
part A pins: 1 DATA (io), 3 CLK (in), 4 TDI (in), 5 TMS (in), 6 TCK (in), 7 ~{CF} (oc), 8 ~{RESET}/OE (in), 10 ~{CE} (in), 11 GND (power), 13 ~{CEO}, 17 TDO (out), 18 VCCINT (power), 19 VCCO (power), 20 VCCJ (power)
part B pins: 2 NC, 9 NC, 12 NC, 14 NC, 15 NC, 16 NC

## AT18F010-30XU
designator U?
FPGA Configuration Flash Memory, 1-MBit Memory, 20-Pin TSSOP, Industrial Grade (-40°C to 85°C)
footprint 20A2_N (TSOP, 20-Leads, Body 6.5x4.4mm, Pitch 0.65mm, IPC Medium Density)
footprint 20A2_L (TSOP, 20-Leads, Body 6.5x4.4mm, Pitch 0.65mm, IPC High Density)
footprint 20A2_M (TSOP, 20-Leads, Body 6.5x4.4mm, Pitch 0.65mm, IPC Low Density)
part A pins: 1 DATA (io), 3 CLK (in), 4 TDI (in), 5 TMS (in), 6 TCK (in), 7 ~{CF} (oc), 8 ~{RESET}/OE (in), 10 ~{CE} (in), 11 GND (power), 13 ~{CEO}, 17 TDO (out), 18 VCCINT (power), 19 VCCO (power), 20 VCCJ (power)
part B pins: 2 NC, 9 NC, 12 NC, 14 NC, 15 NC, 16 NC

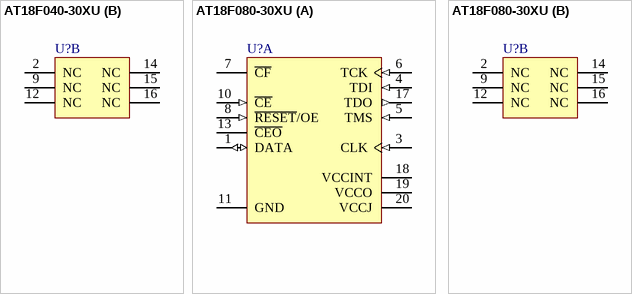
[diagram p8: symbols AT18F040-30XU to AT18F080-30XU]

## AT18F040-30XU
designator U?
FPGA Configuration Flash Memory, 4-MBit Memory, 20-Pin TSSOP, Industrial Grade (-40°C to 85°C)
footprint 20A2_N (TSOP, 20-Leads, Body 6.5x4.4mm, Pitch 0.65mm, IPC Medium Density)
footprint 20A2_L (TSOP, 20-Leads, Body 6.5x4.4mm, Pitch 0.65mm, IPC High Density)
footprint 20A2_M (TSOP, 20-Leads, Body 6.5x4.4mm, Pitch 0.65mm, IPC Low Density)
part A pins: 1 DATA (io), 3 CLK (in), 4 TDI (in), 5 TMS (in), 6 TCK (in), 7 ~{CF} (oc), 8 ~{RESET}/OE (in), 10 ~{CE} (in), 11 GND (power), 13 ~{CEO}, 17 TDO (out), 18 VCCINT (power), 19 VCCO (power), 20 VCCJ (power)
part B pins: 2 NC, 9 NC, 12 NC, 14 NC, 15 NC, 16 NC

## AT18F080-30XU
designator U?
FPGA Configuration Flash Memory, 7-MBit Memory, 20-Pin TSSOP, Industrial Grade (-40°C to 85°C)
footprint 20A2_N (TSOP, 20-Leads, Body 6.5x4.4mm, Pitch 0.65mm, IPC Medium Density)
footprint 20A2_L (TSOP, 20-Leads, Body 6.5x4.4mm, Pitch 0.65mm, IPC High Density)
footprint 20A2_M (TSOP, 20-Leads, Body 6.5x4.4mm, Pitch 0.65mm, IPC Low Density)
part A pins: 1 DATA (io), 3 CLK (in), 4 TDI (in), 5 TMS (in), 6 TCK (in), 7 ~{CF} (oc), 8 ~{RESET}/OE (in), 10 ~{CE} (in), 11 GND (power), 13 ~{CEO}, 17 TDO (out), 18 VCCINT (power), 19 VCCO (power), 20 VCCJ (power)
part B pins: 2 NC, 9 NC, 12 NC, 14 NC, 15 NC, 16 NC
